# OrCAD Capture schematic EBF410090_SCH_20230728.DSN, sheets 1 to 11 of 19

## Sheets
1 12 WLAN BT: size A4; title: 野火_EBF RK3566 底板; rev: V1.0; note: WLAN & BT; note: https://yehuosm.tmall.com
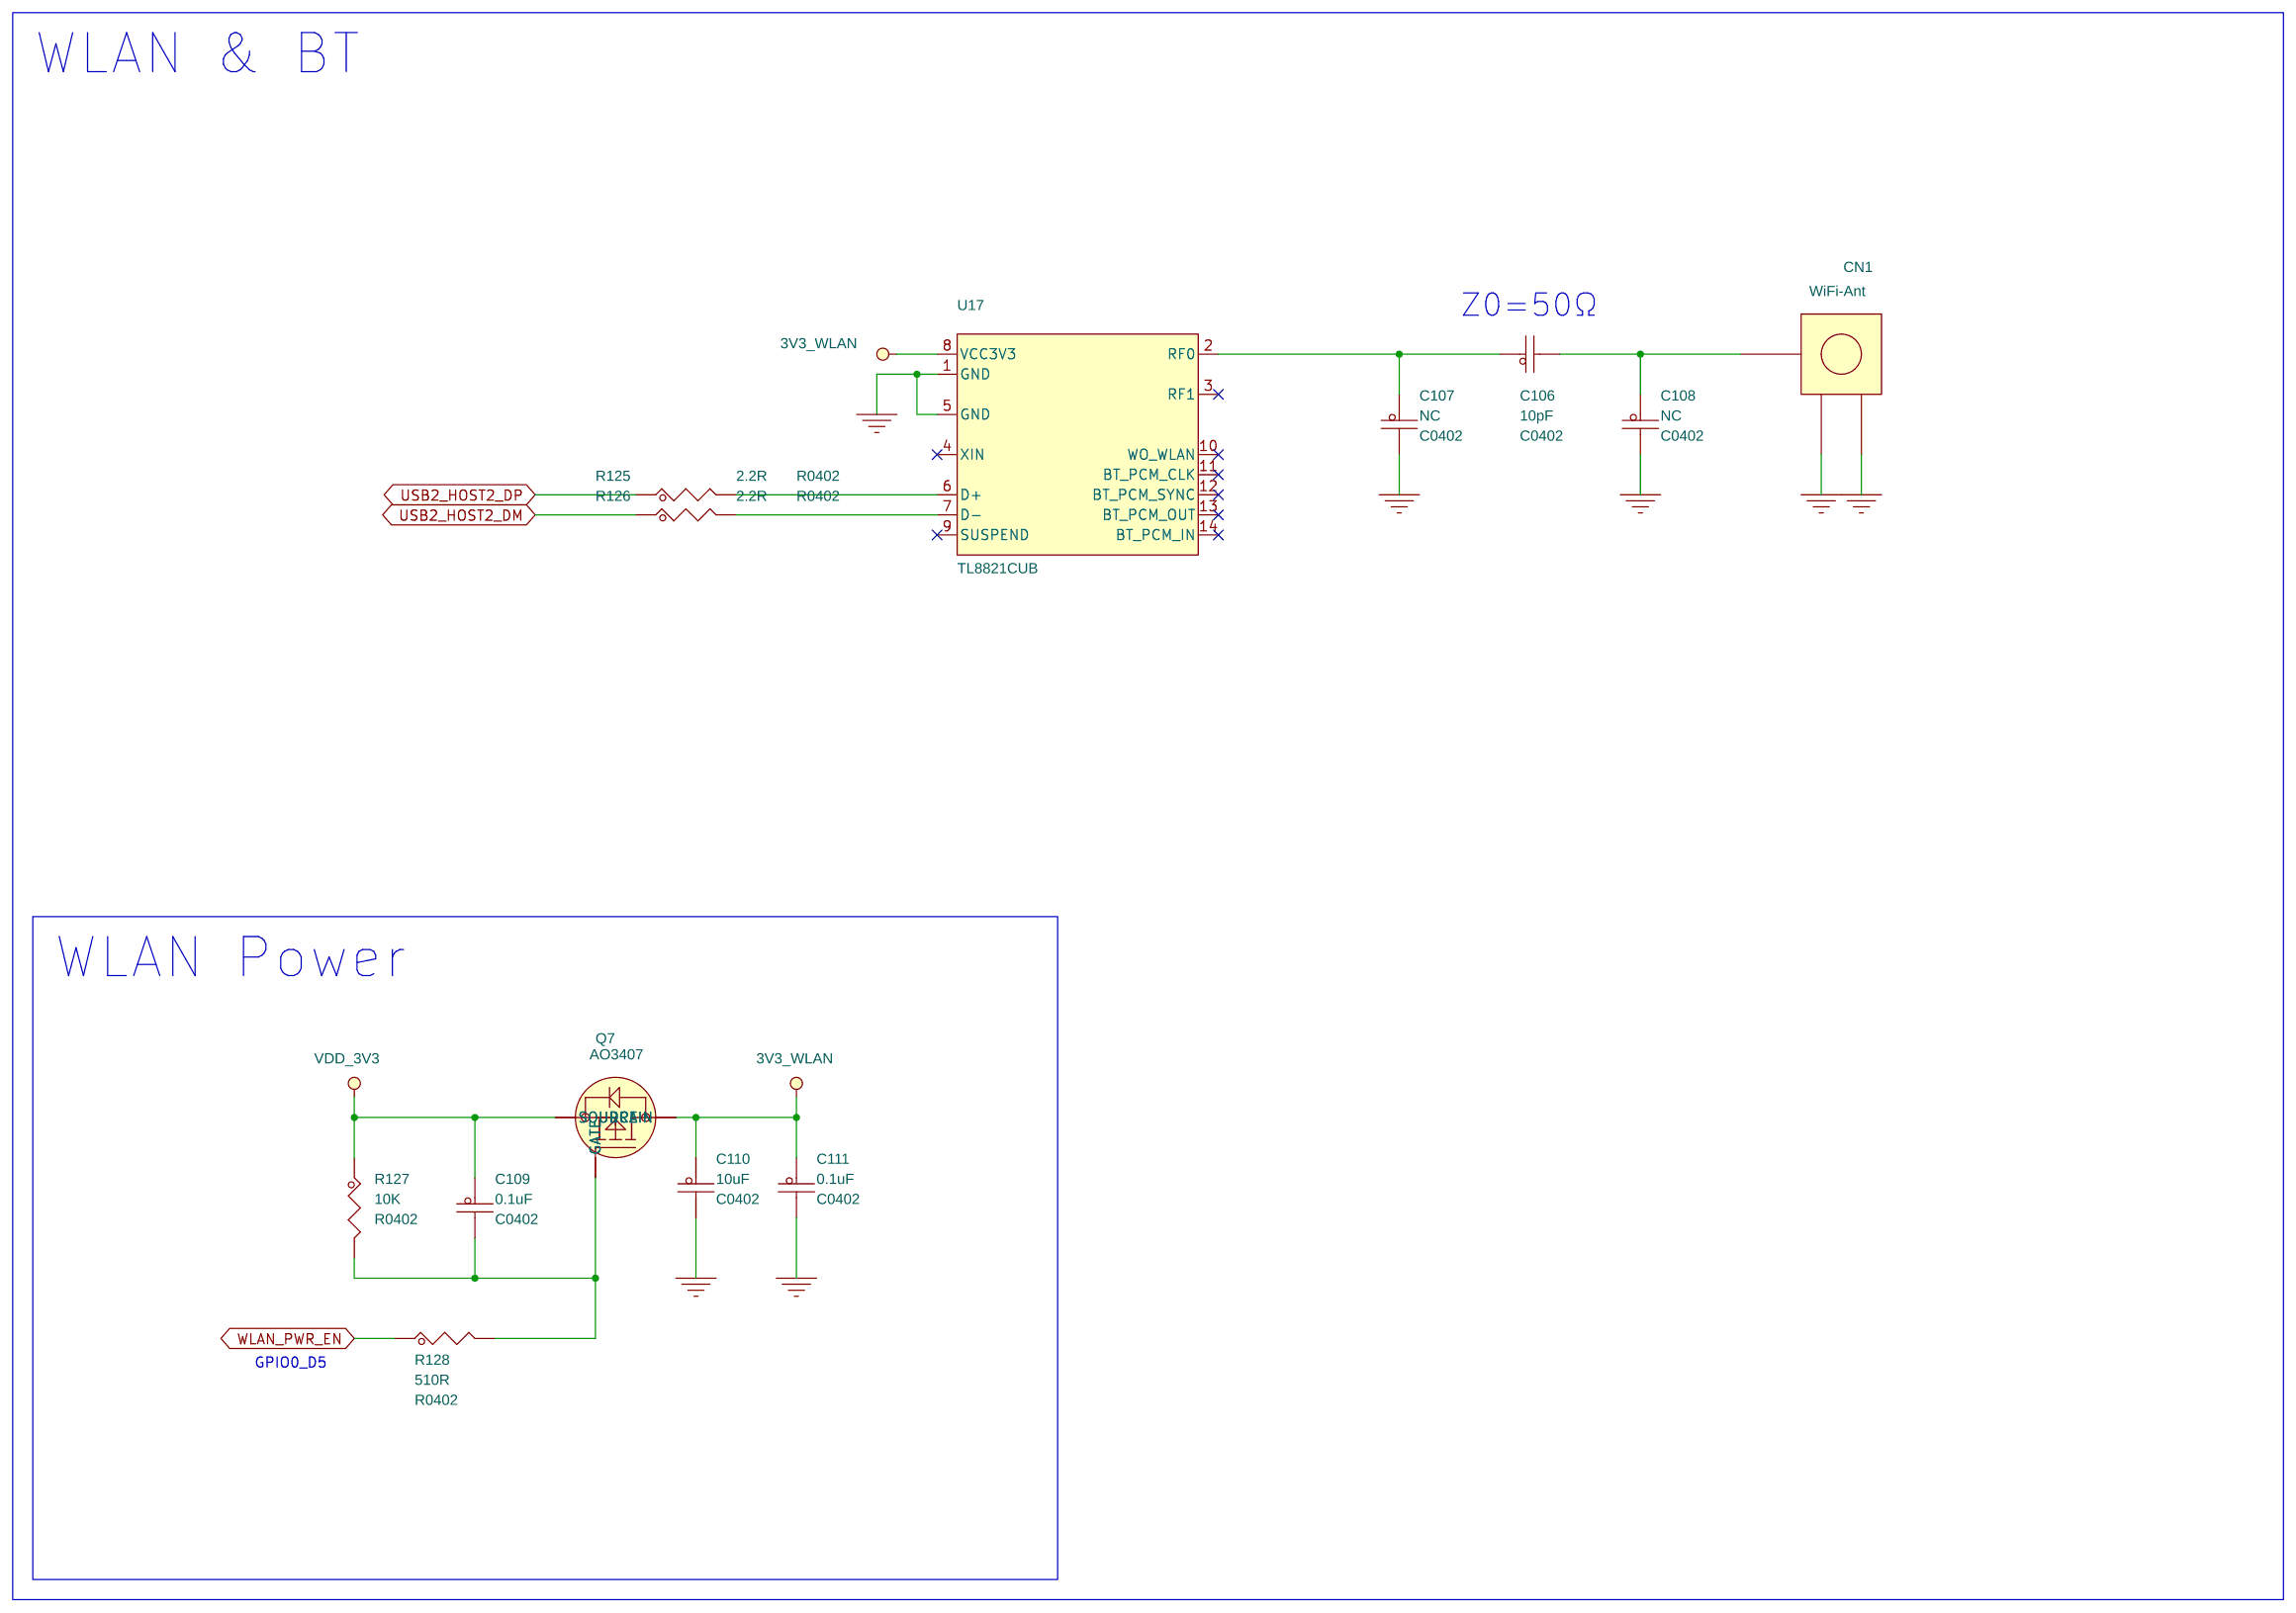
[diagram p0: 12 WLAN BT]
2 01 Content: note: Content
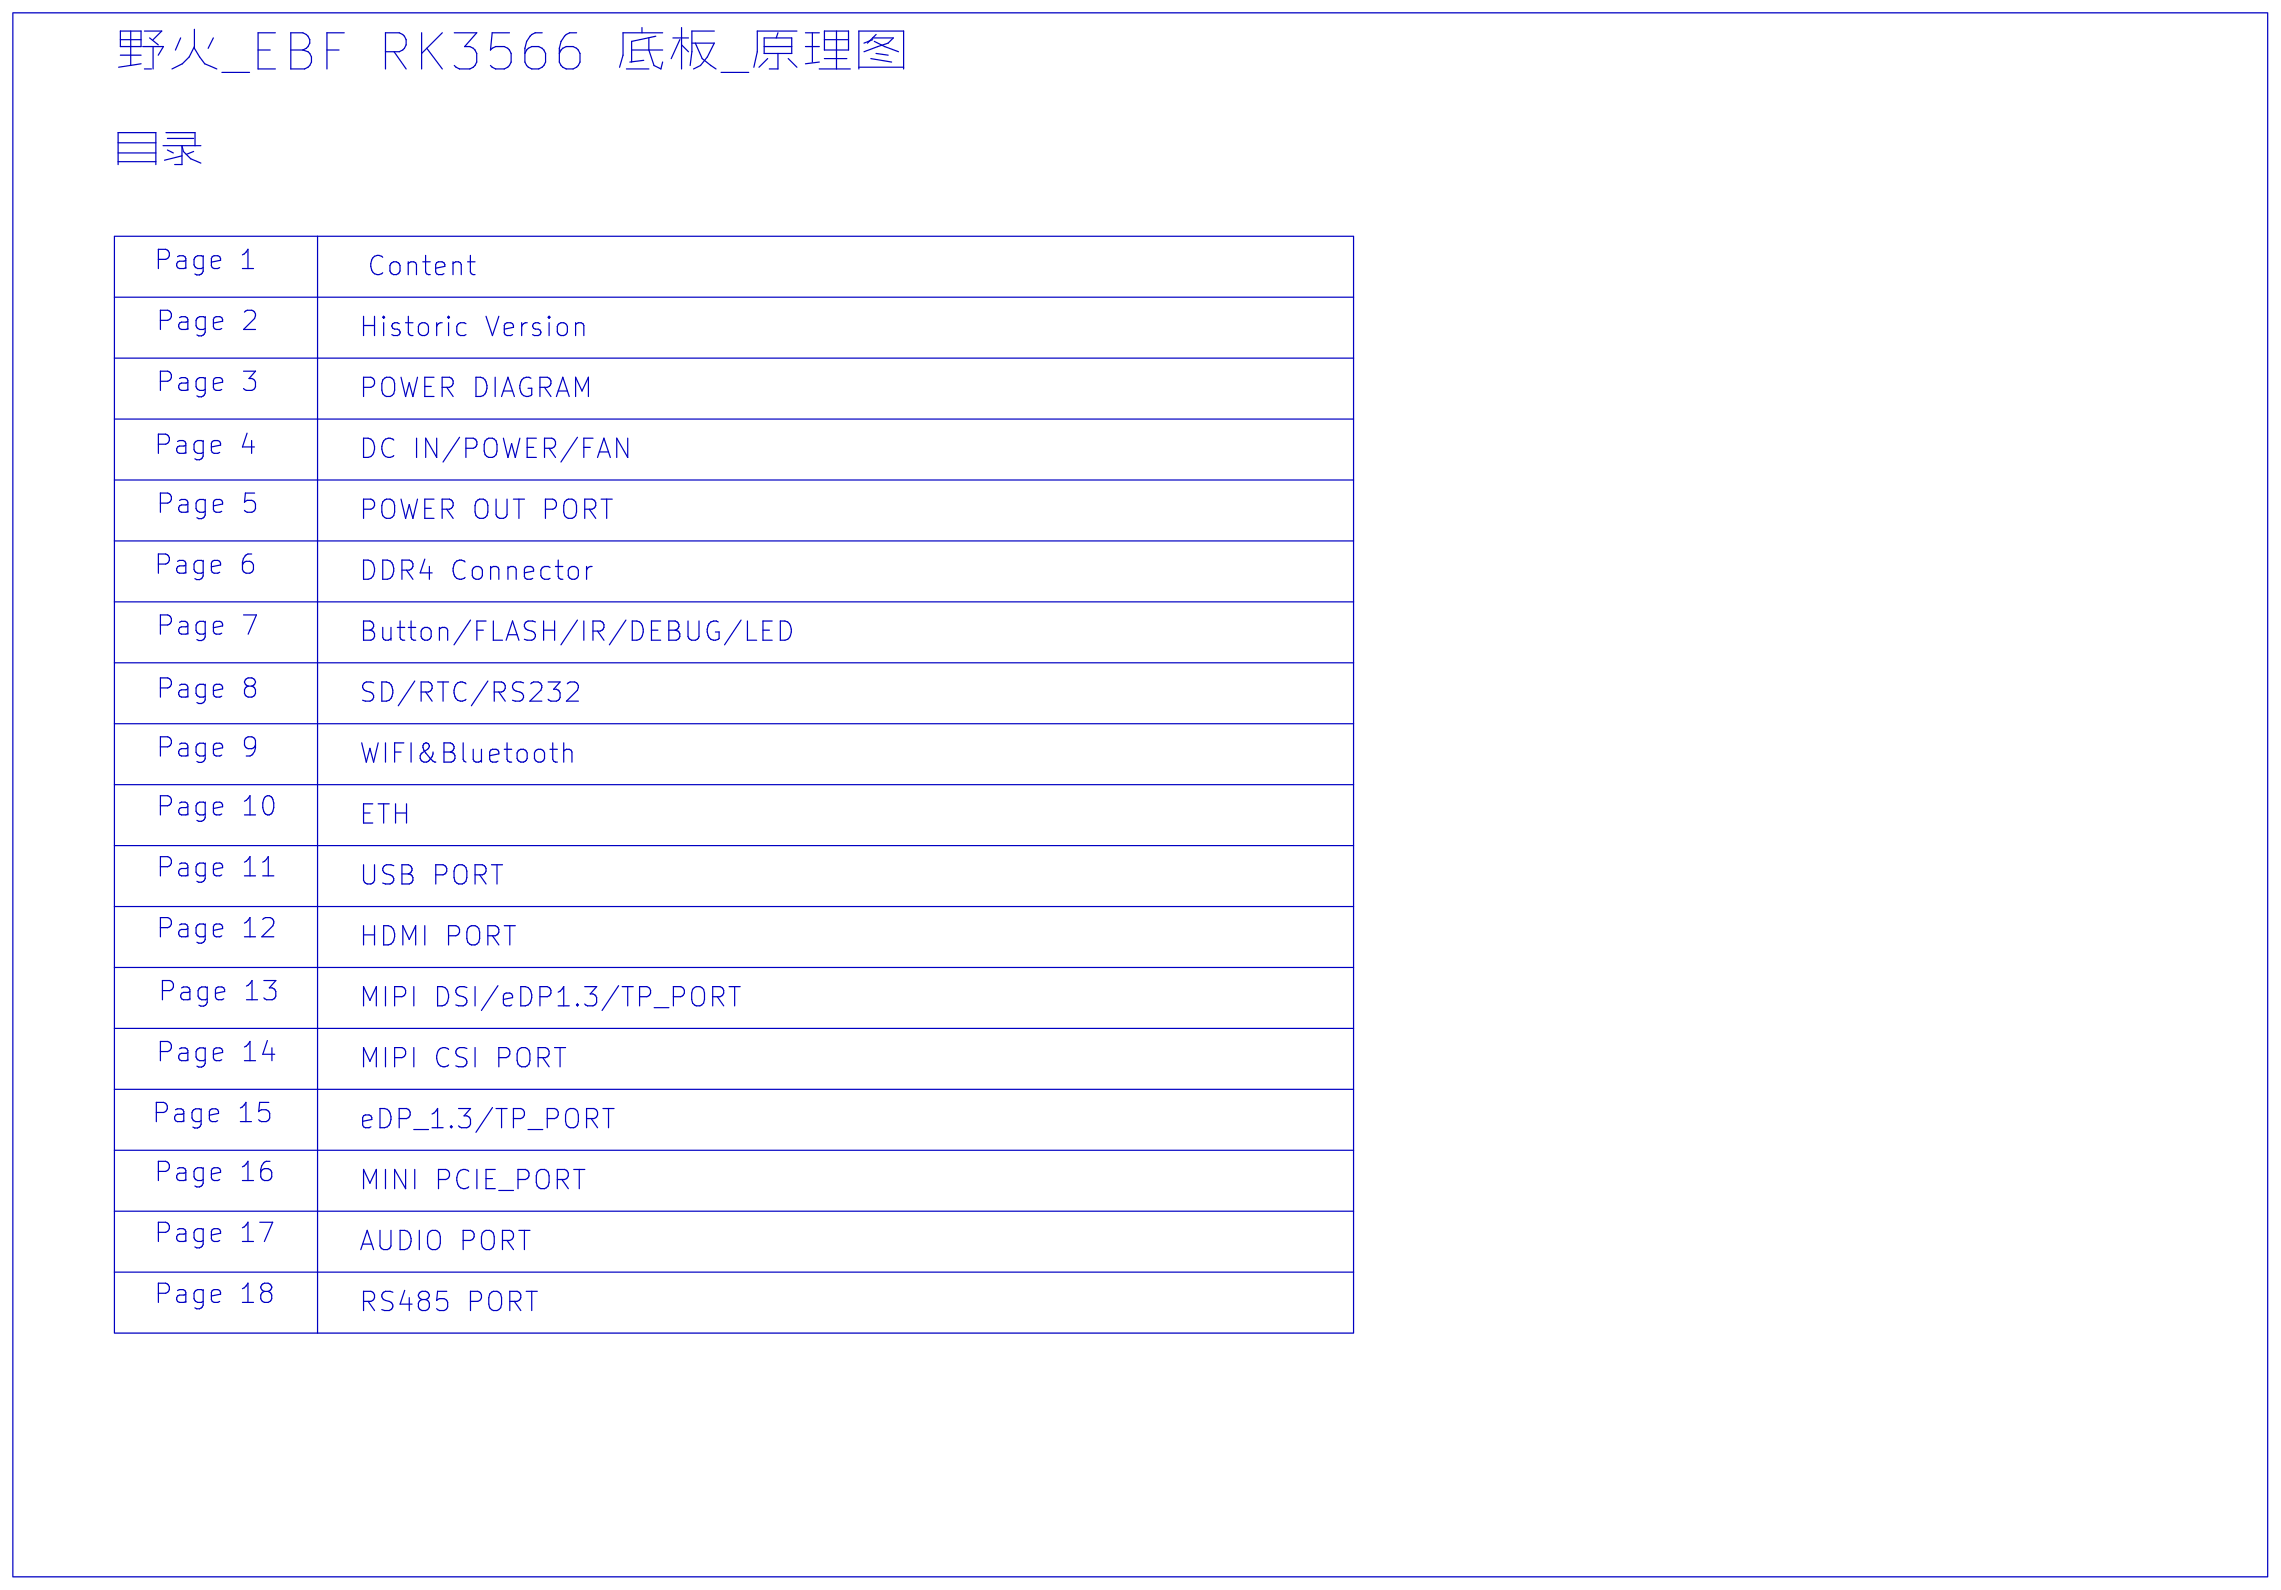
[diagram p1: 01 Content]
3 02 Historic Version: note: Historic Version
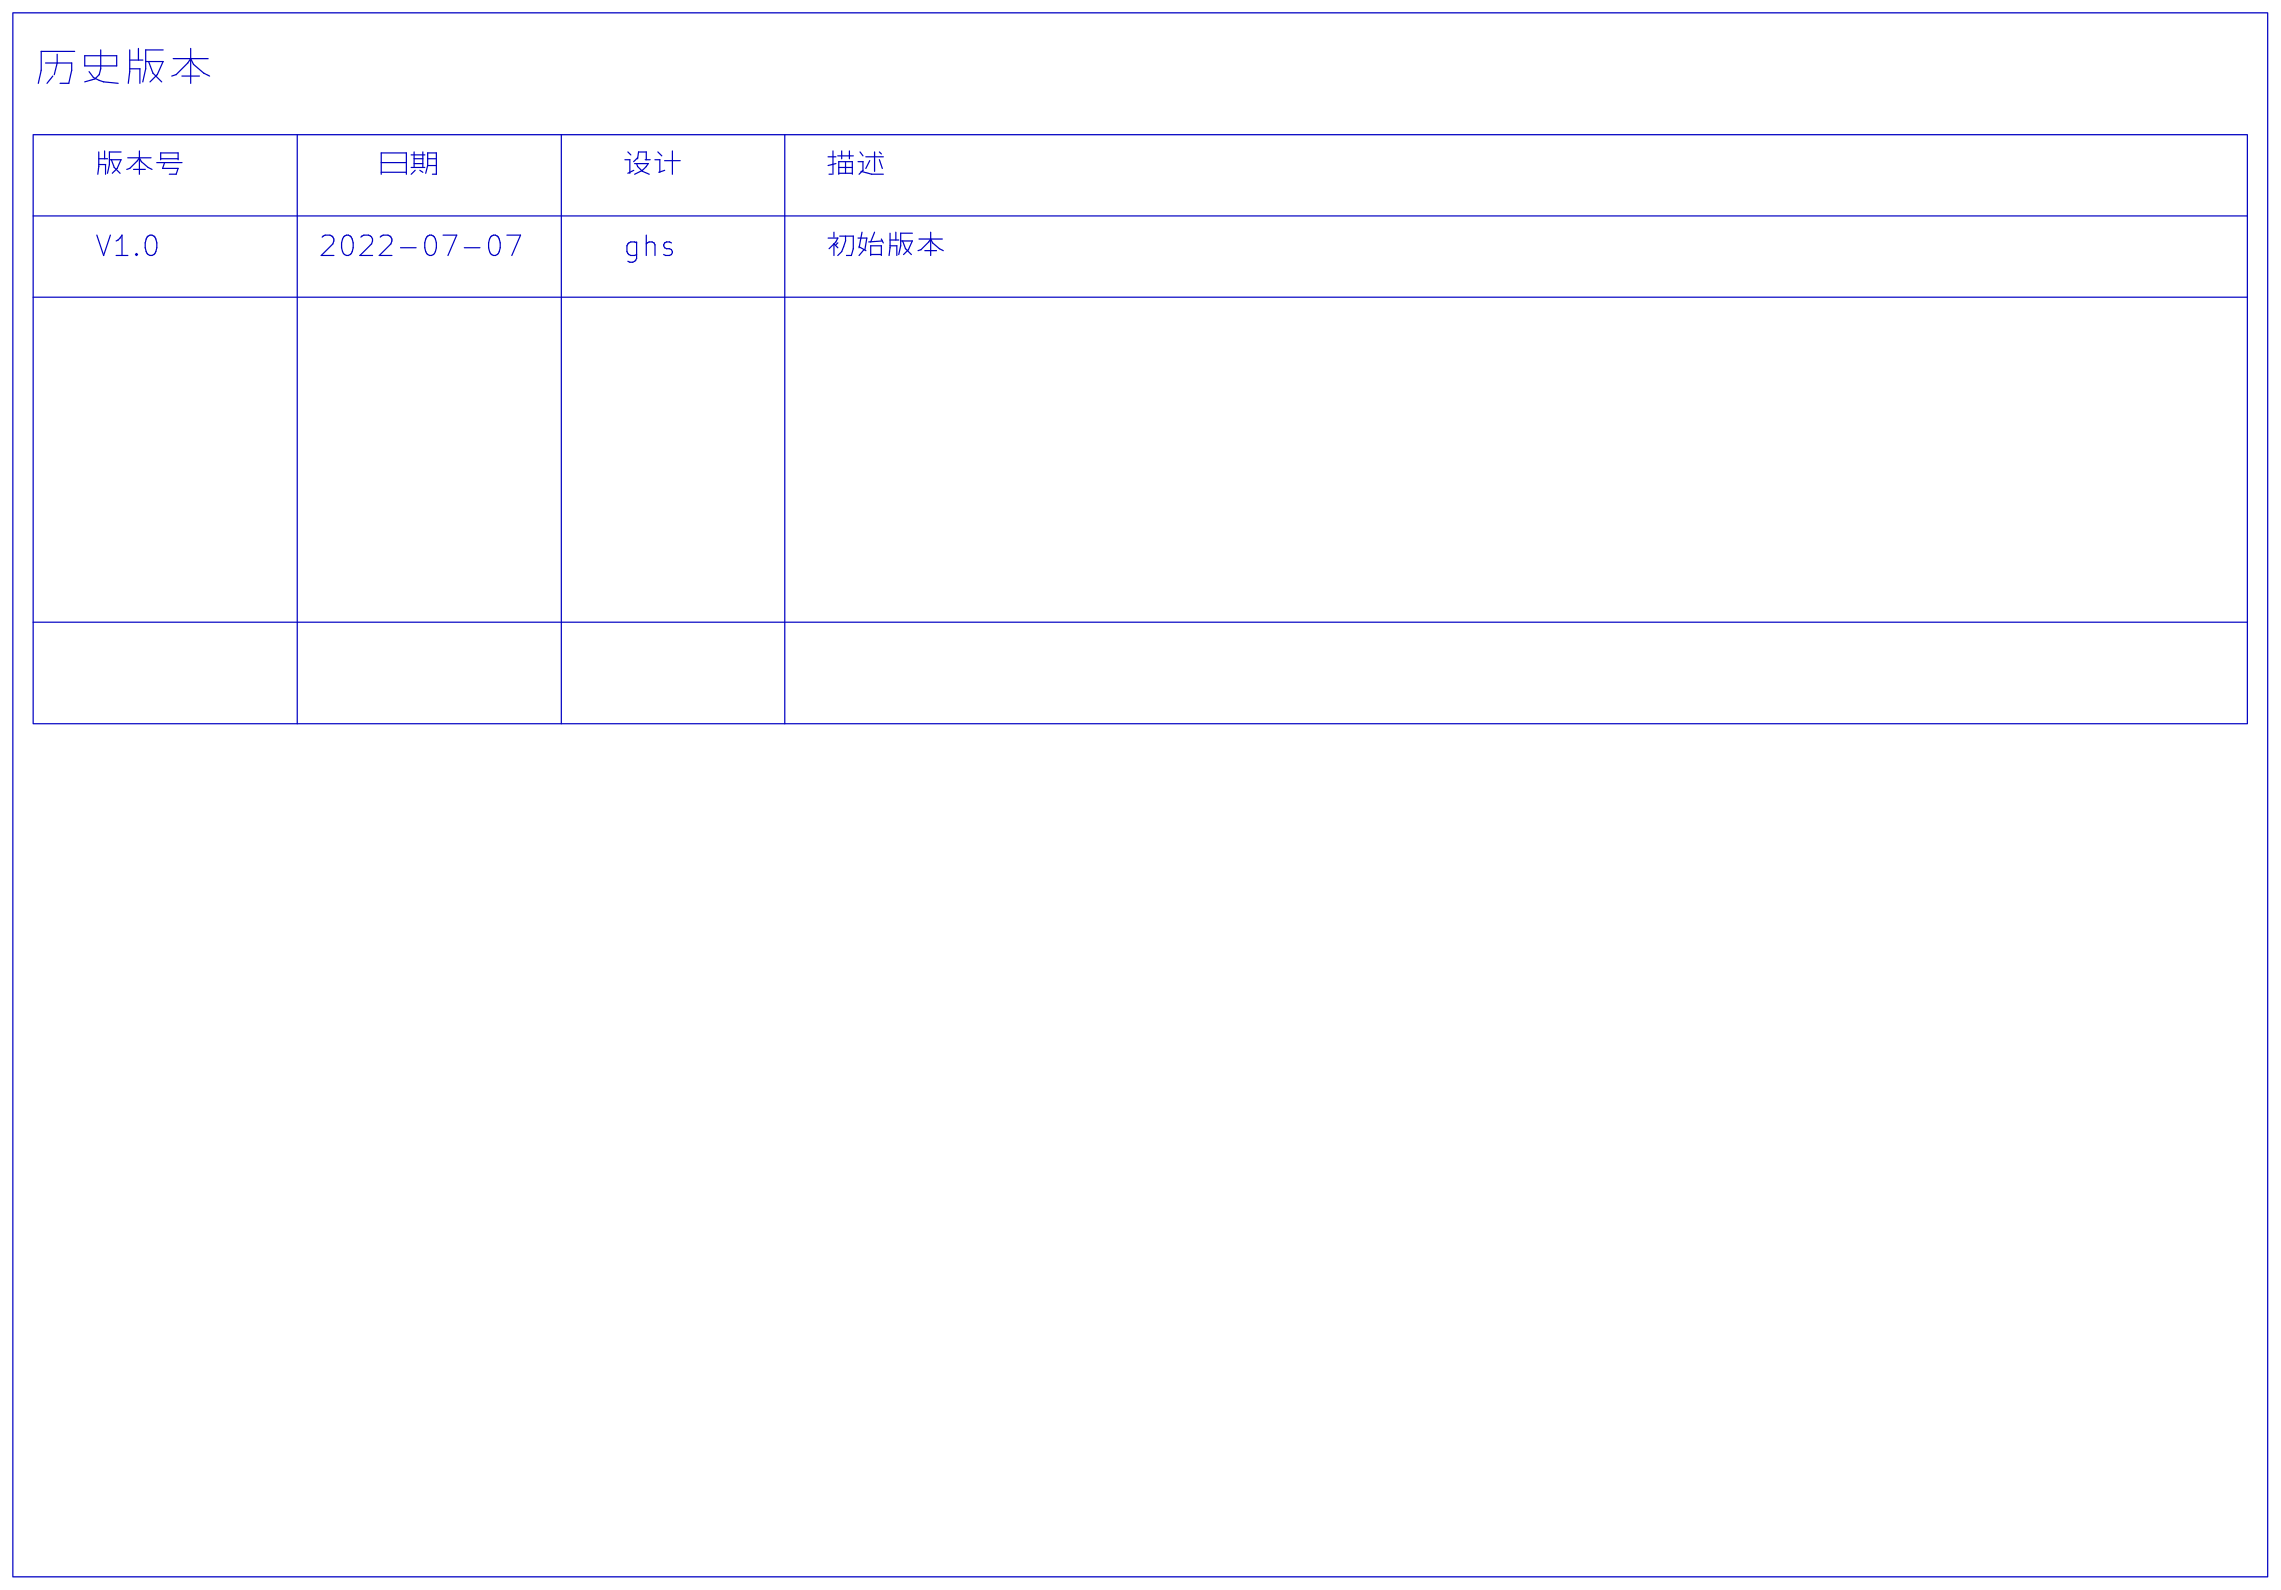
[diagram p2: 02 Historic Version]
4 03 POWER DIAGRAM: note: POWER DIAGRAM
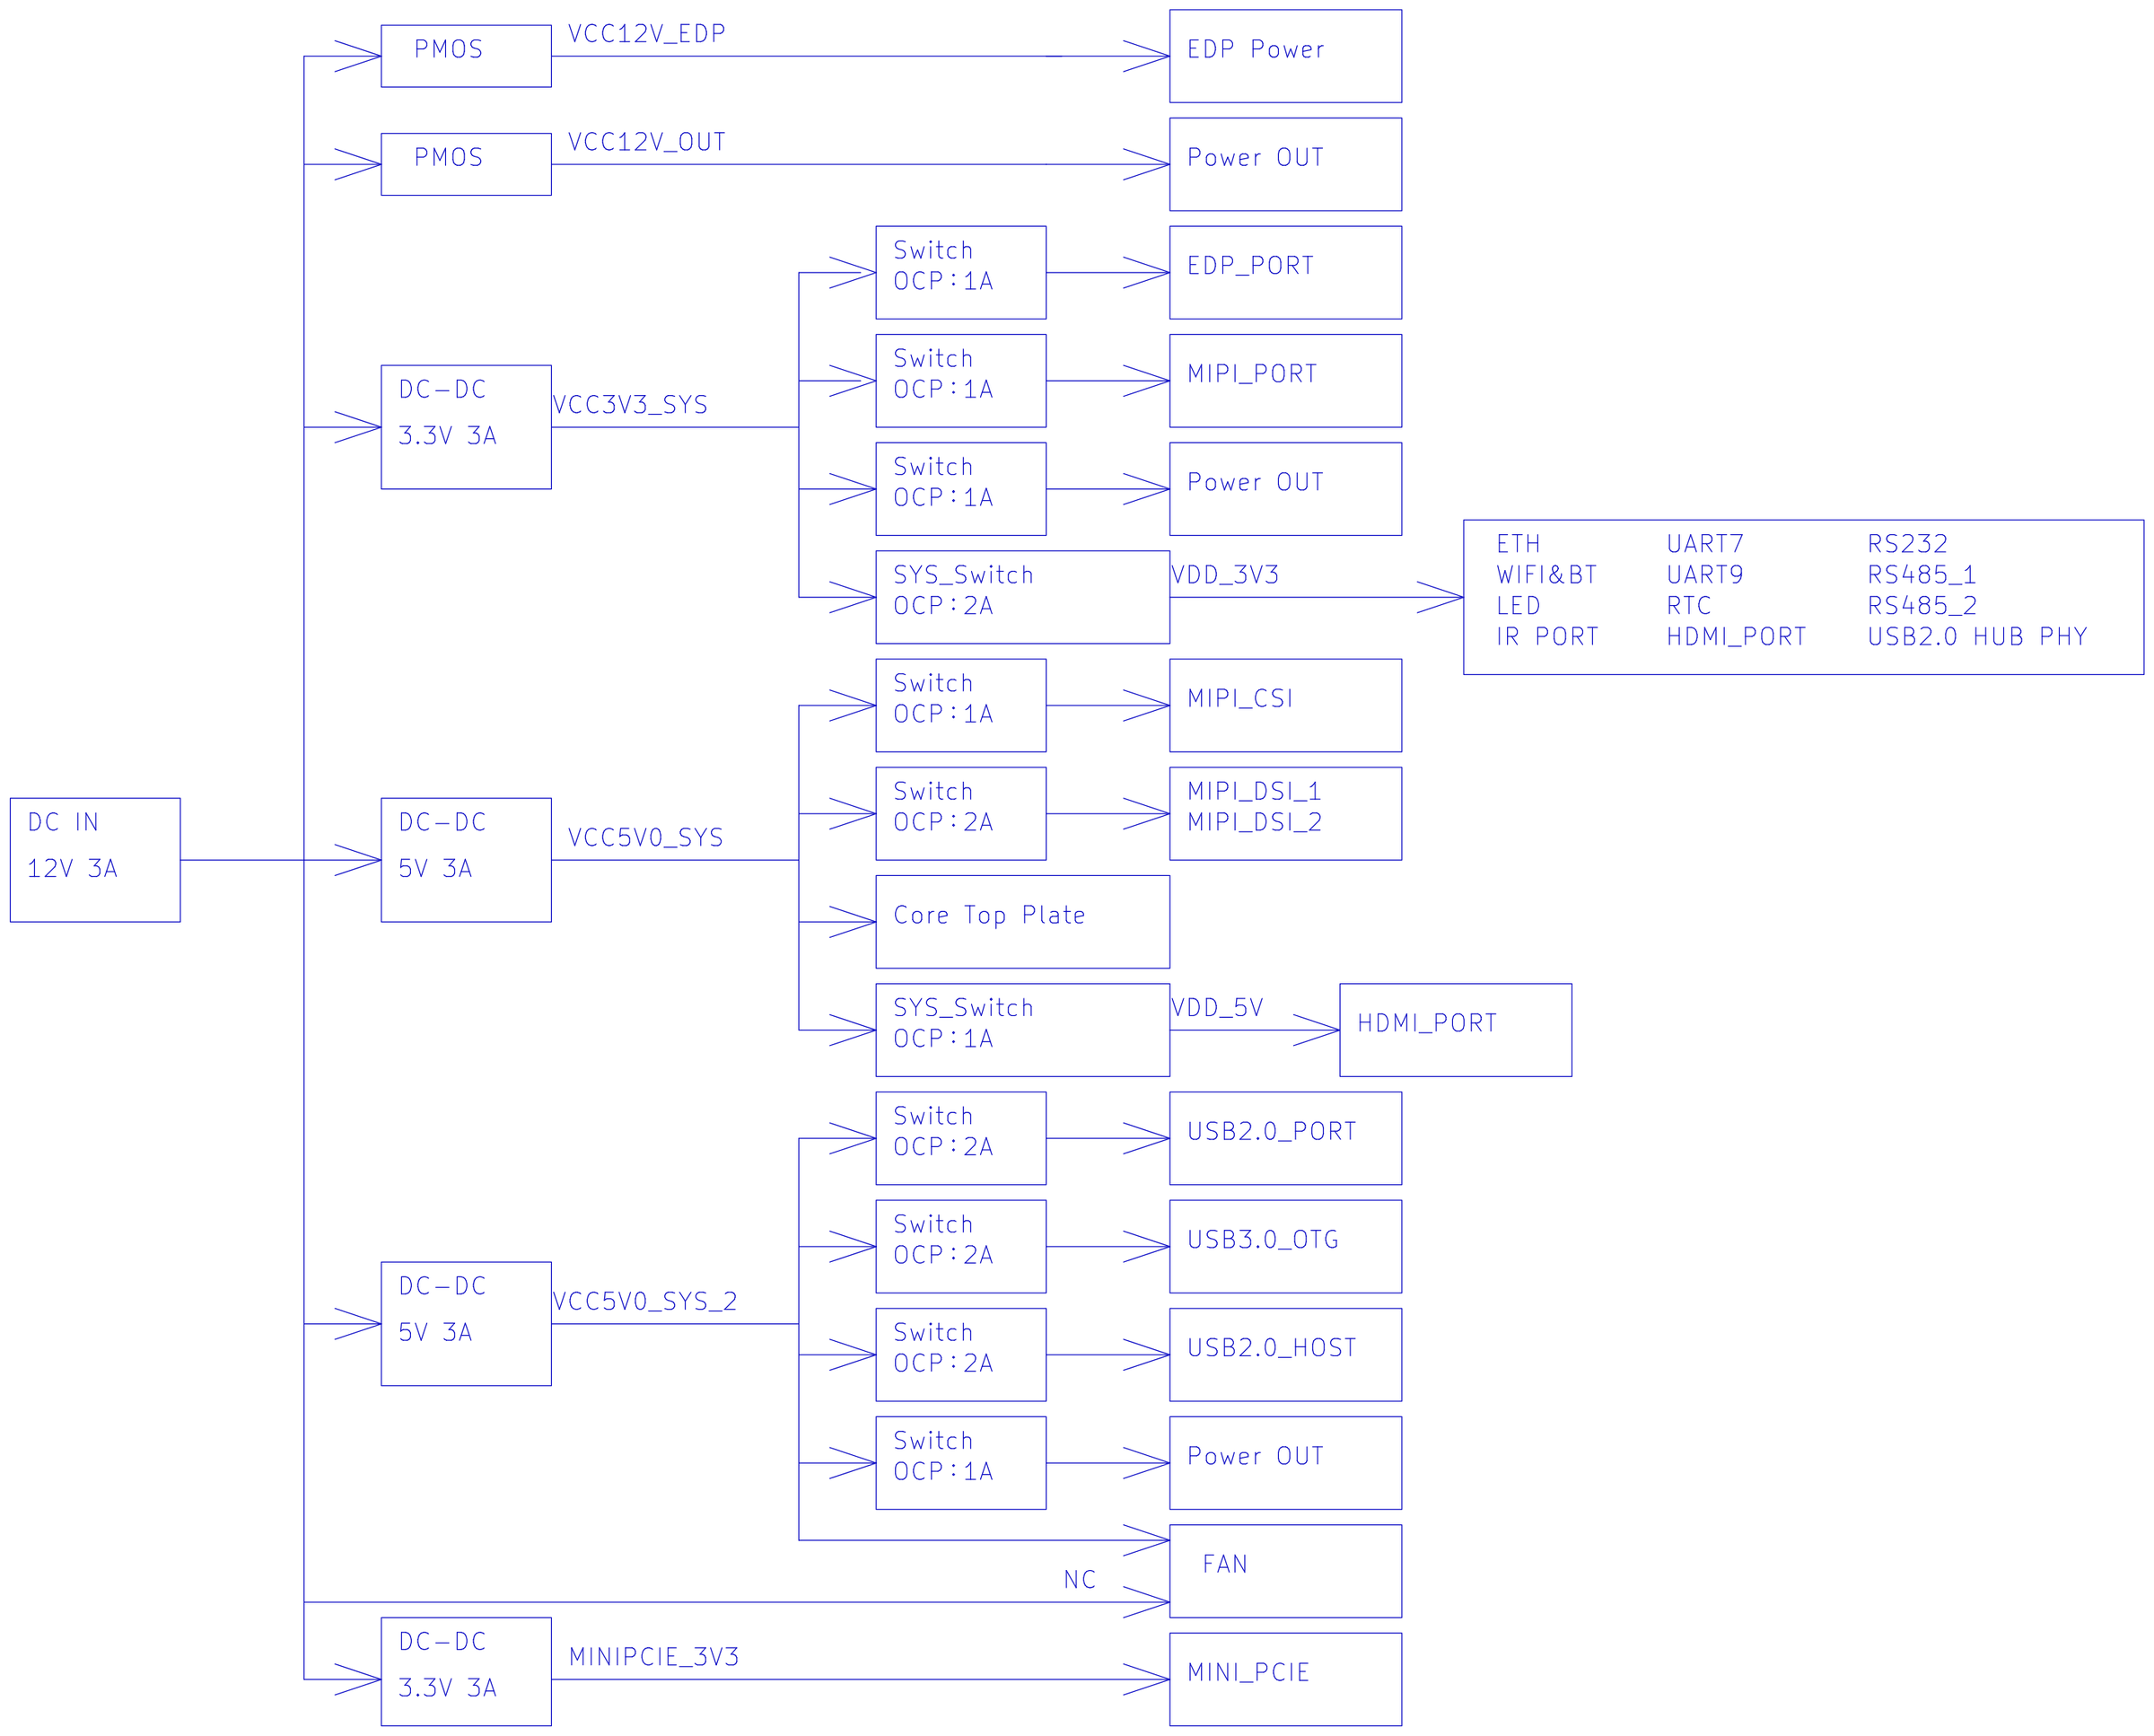
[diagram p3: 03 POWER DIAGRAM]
5 05 POWER OUT PORT: size A4; note: POWER OUT PORT
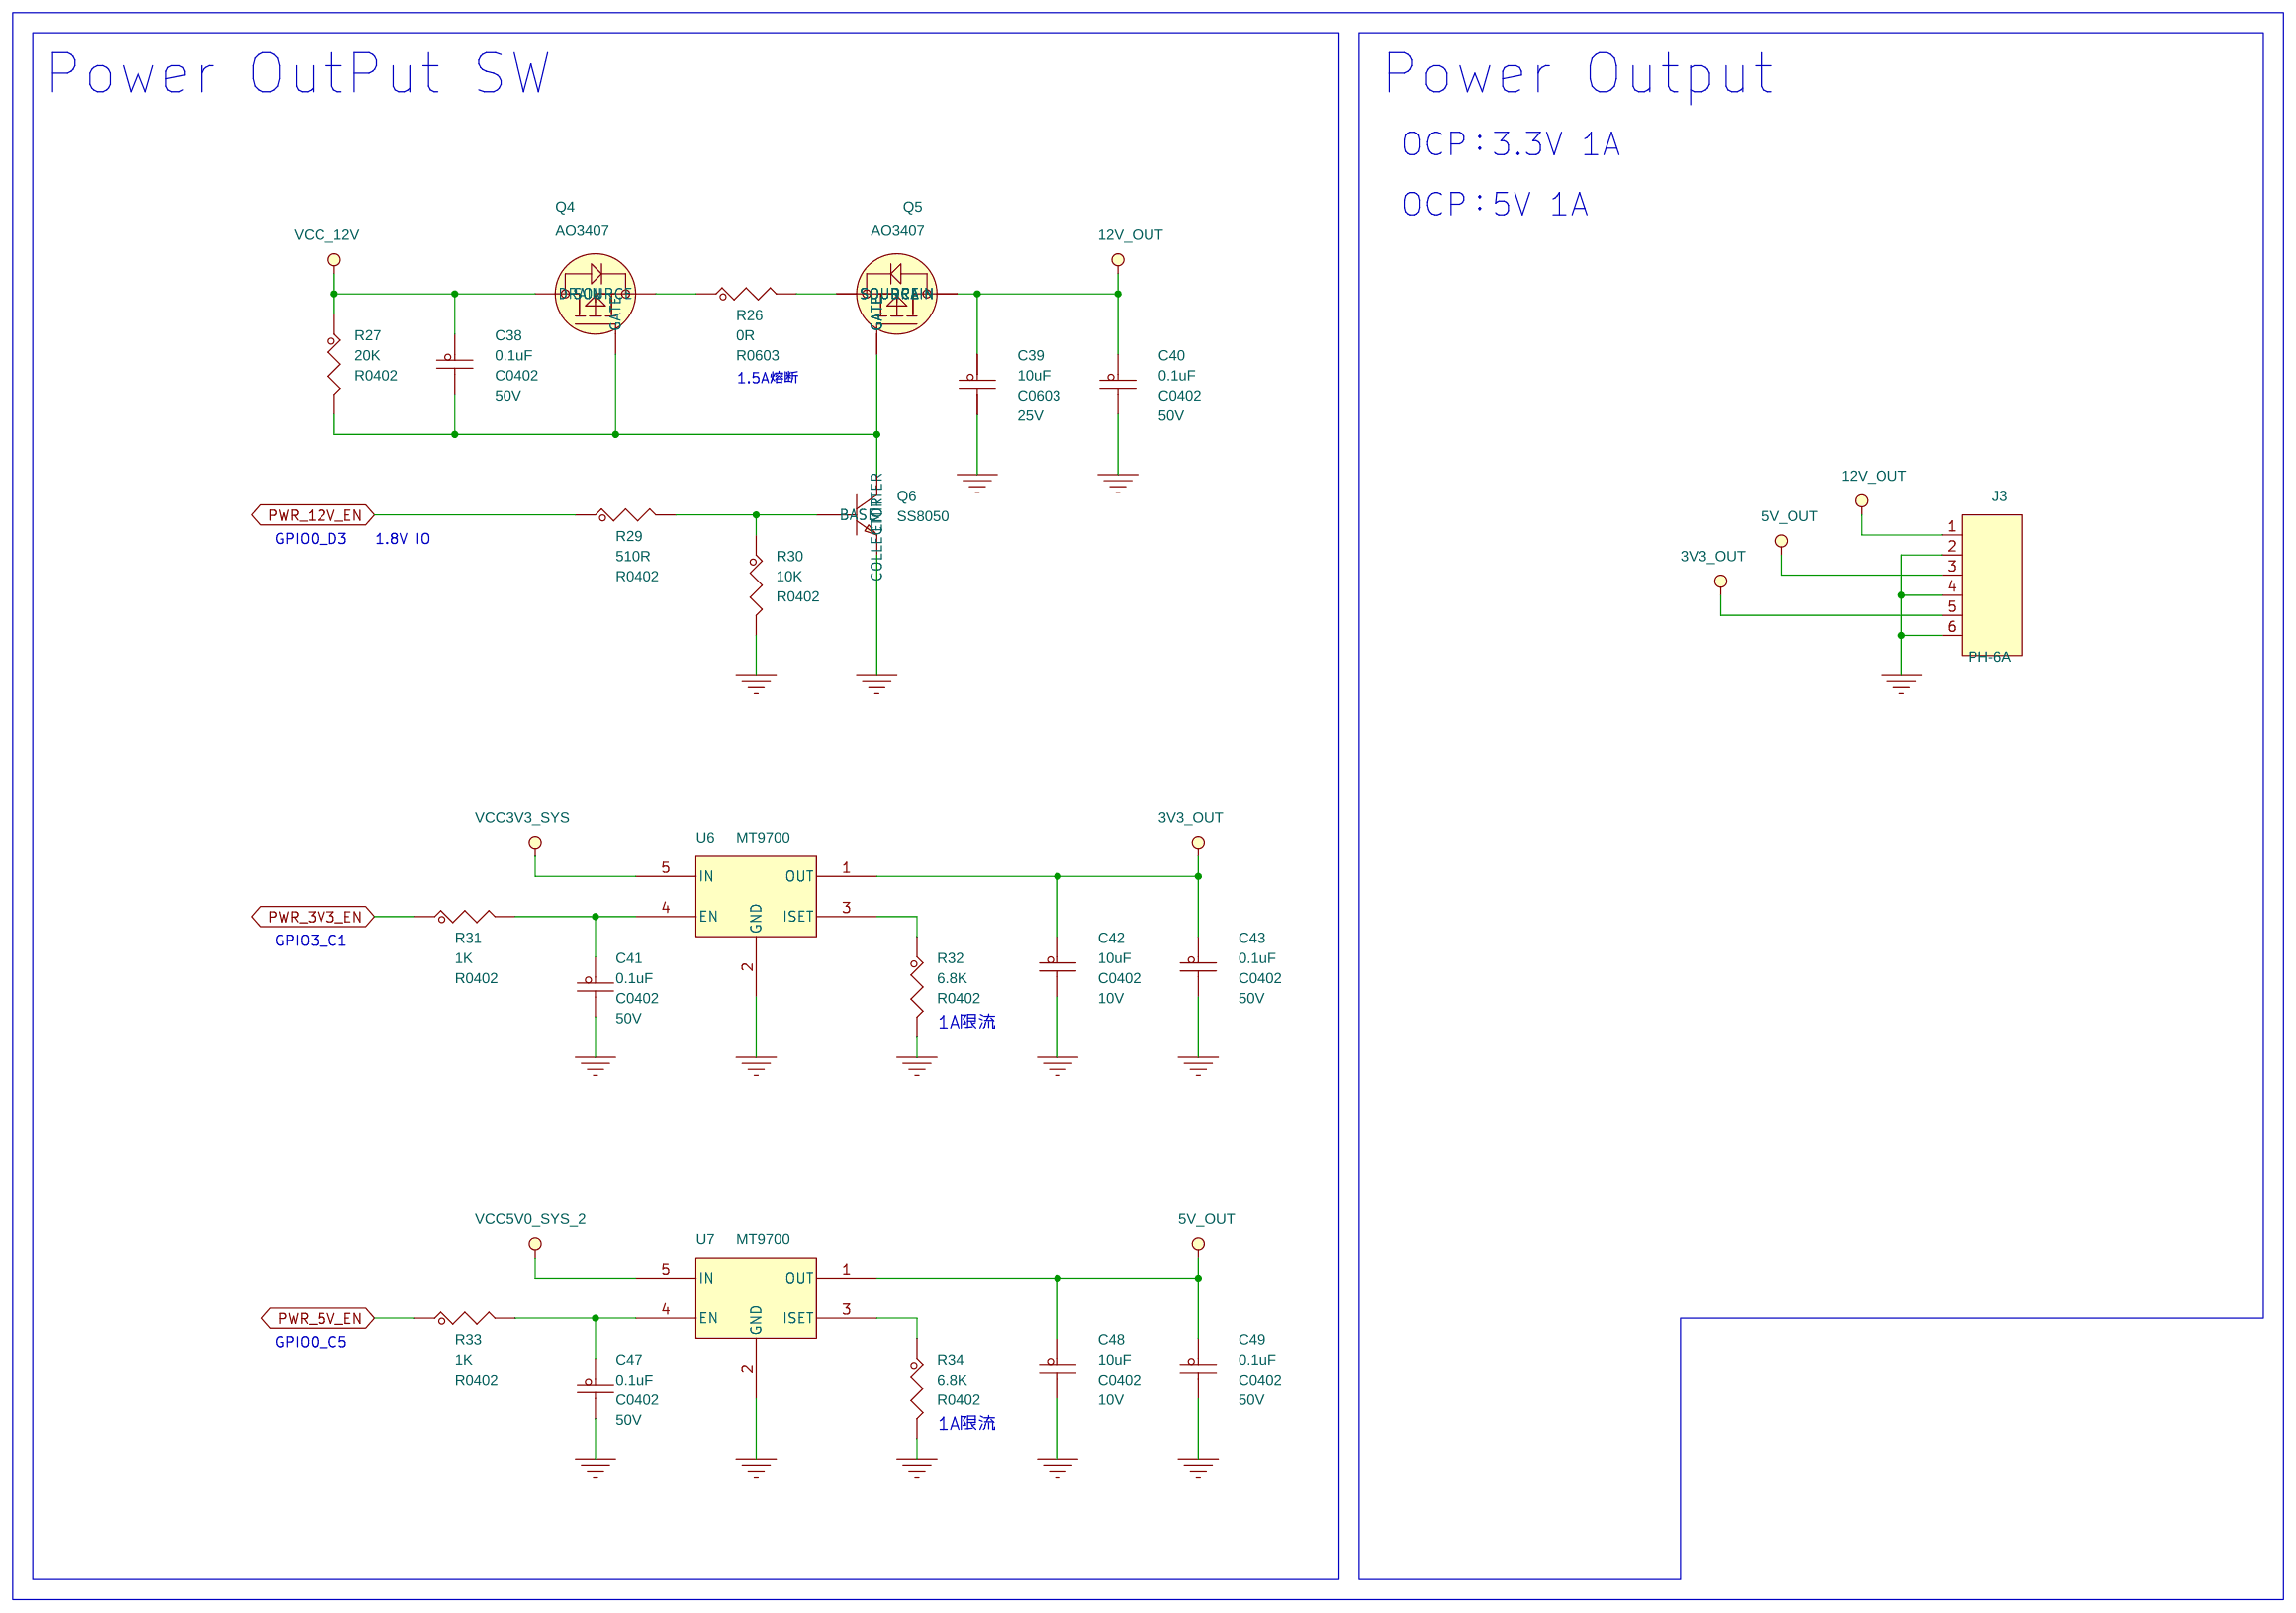
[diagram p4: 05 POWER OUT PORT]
6 06 DDR4 Connector: size A2; title: 野火_EBF RK3568 底板; note: DDR4 Connector
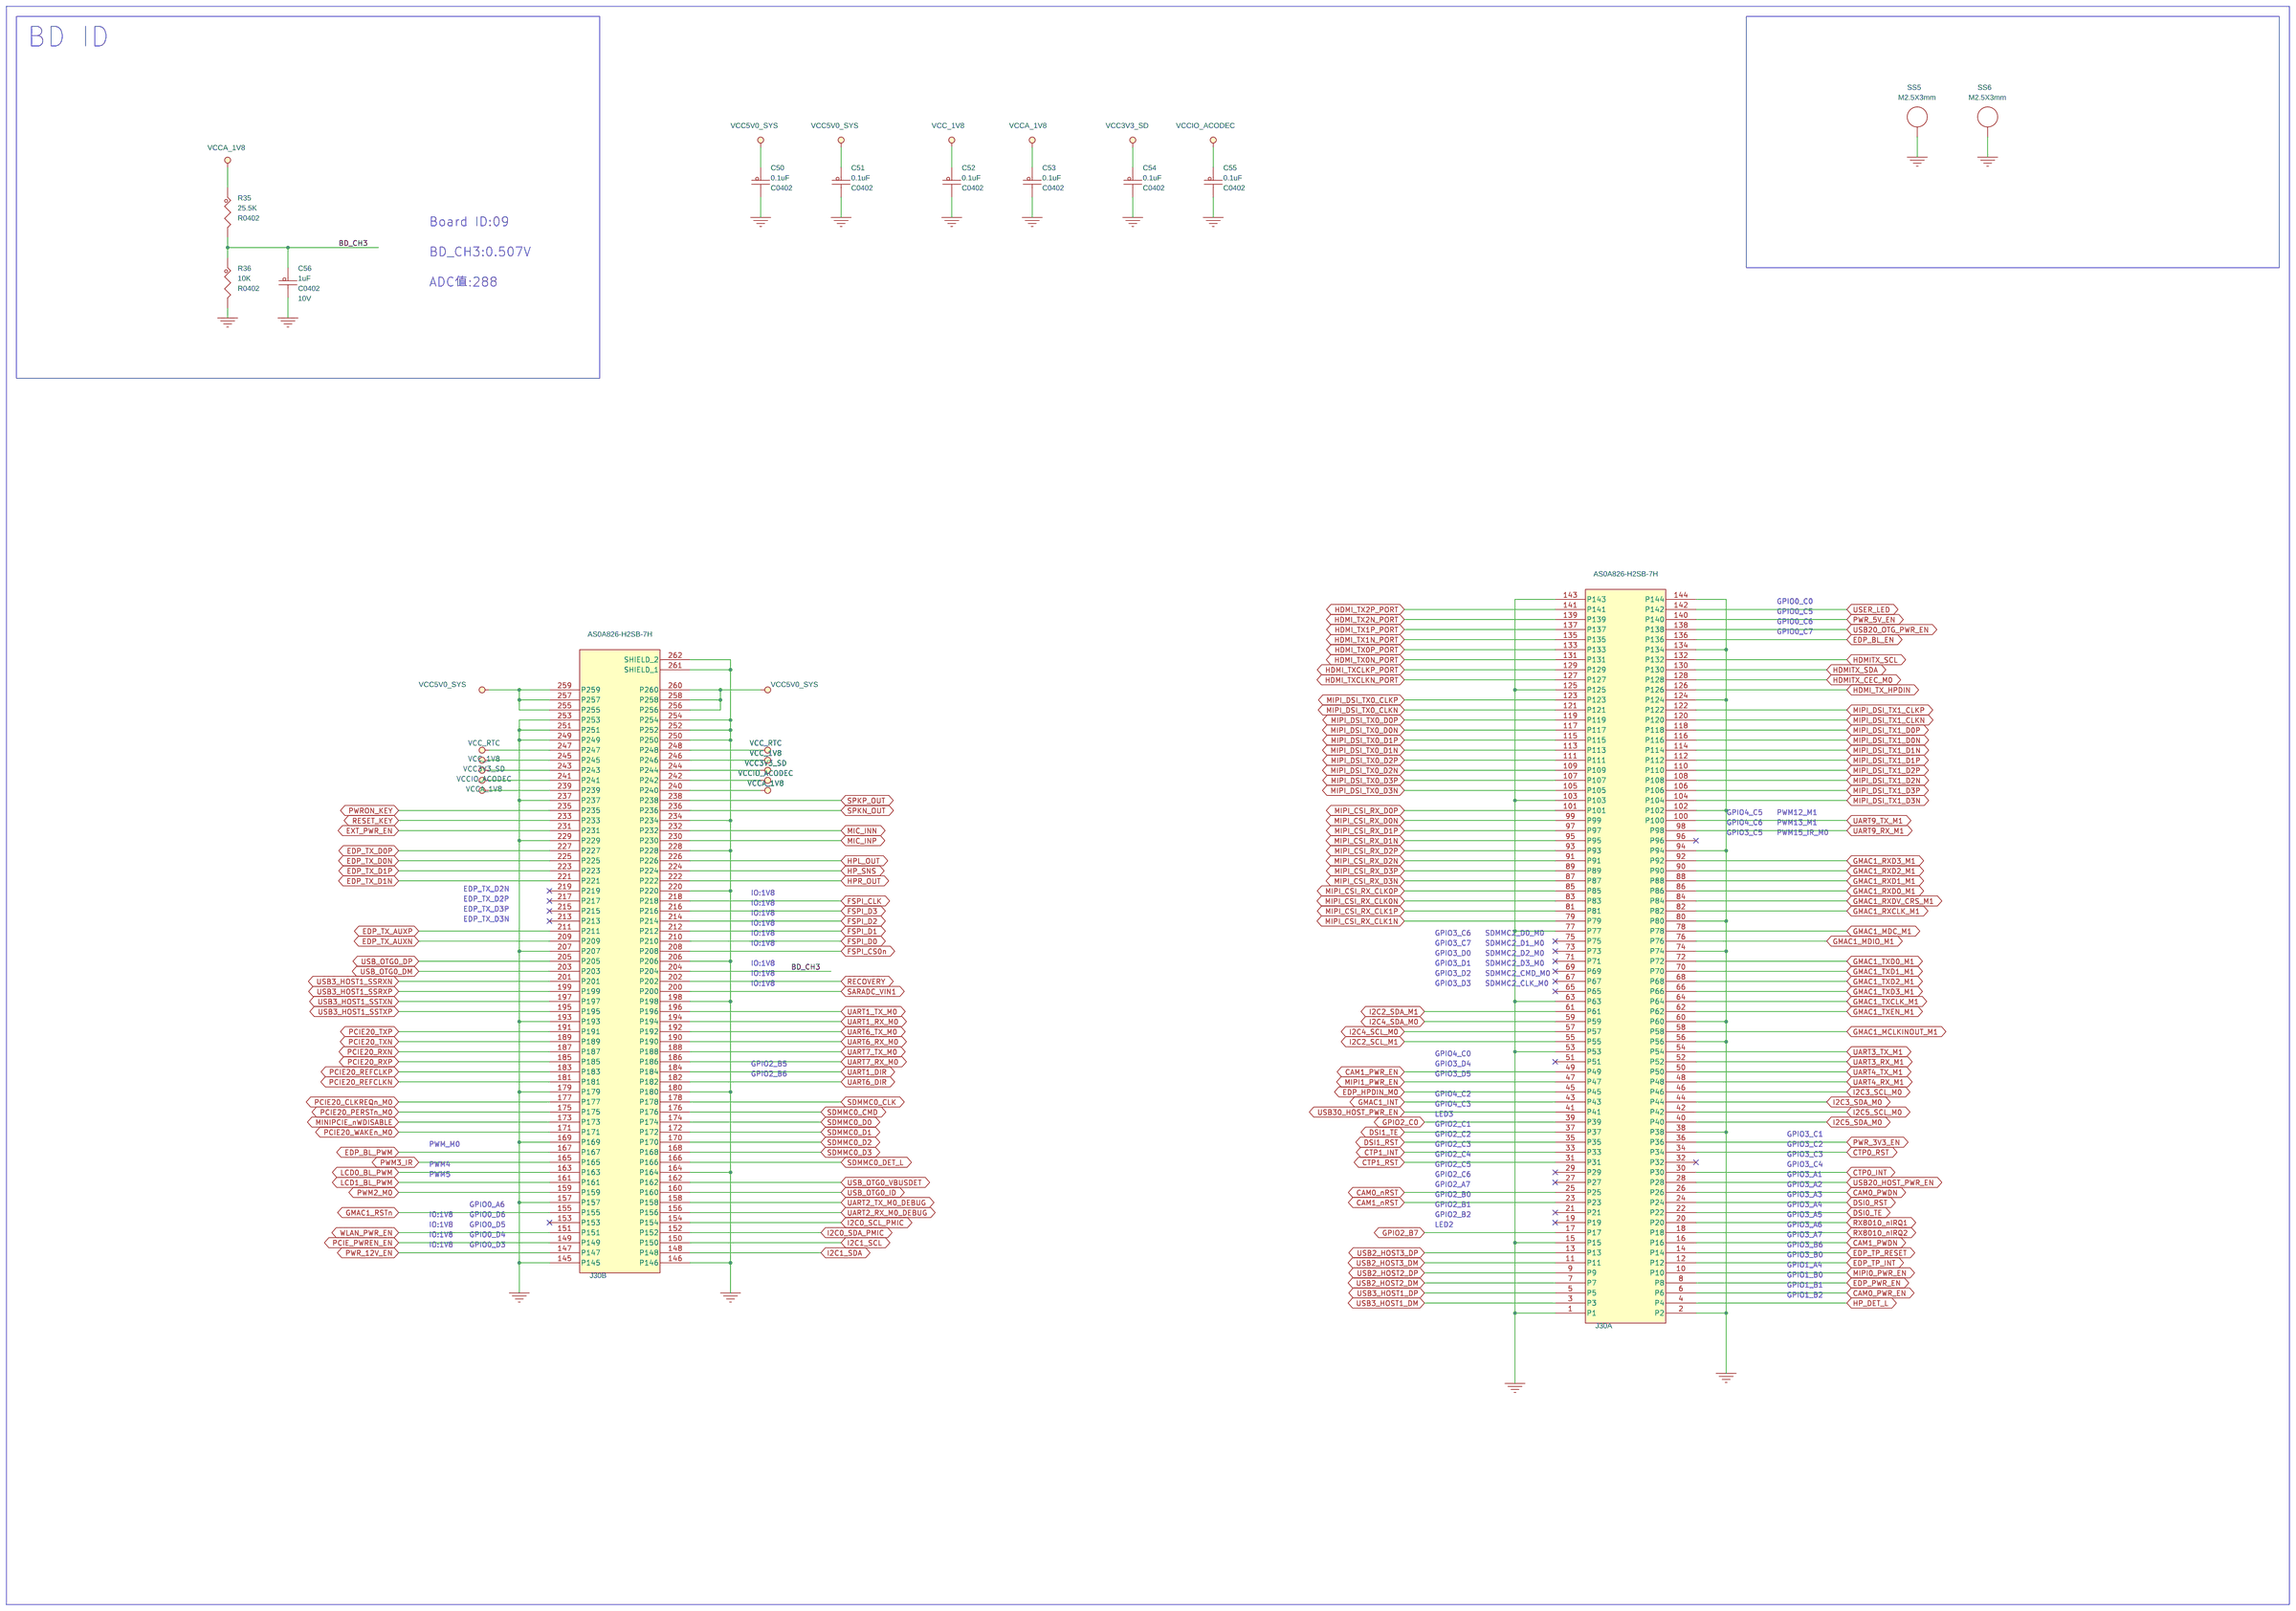
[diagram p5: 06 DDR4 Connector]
7 09 RS485 PORT: size A4; note: RS485 PORT
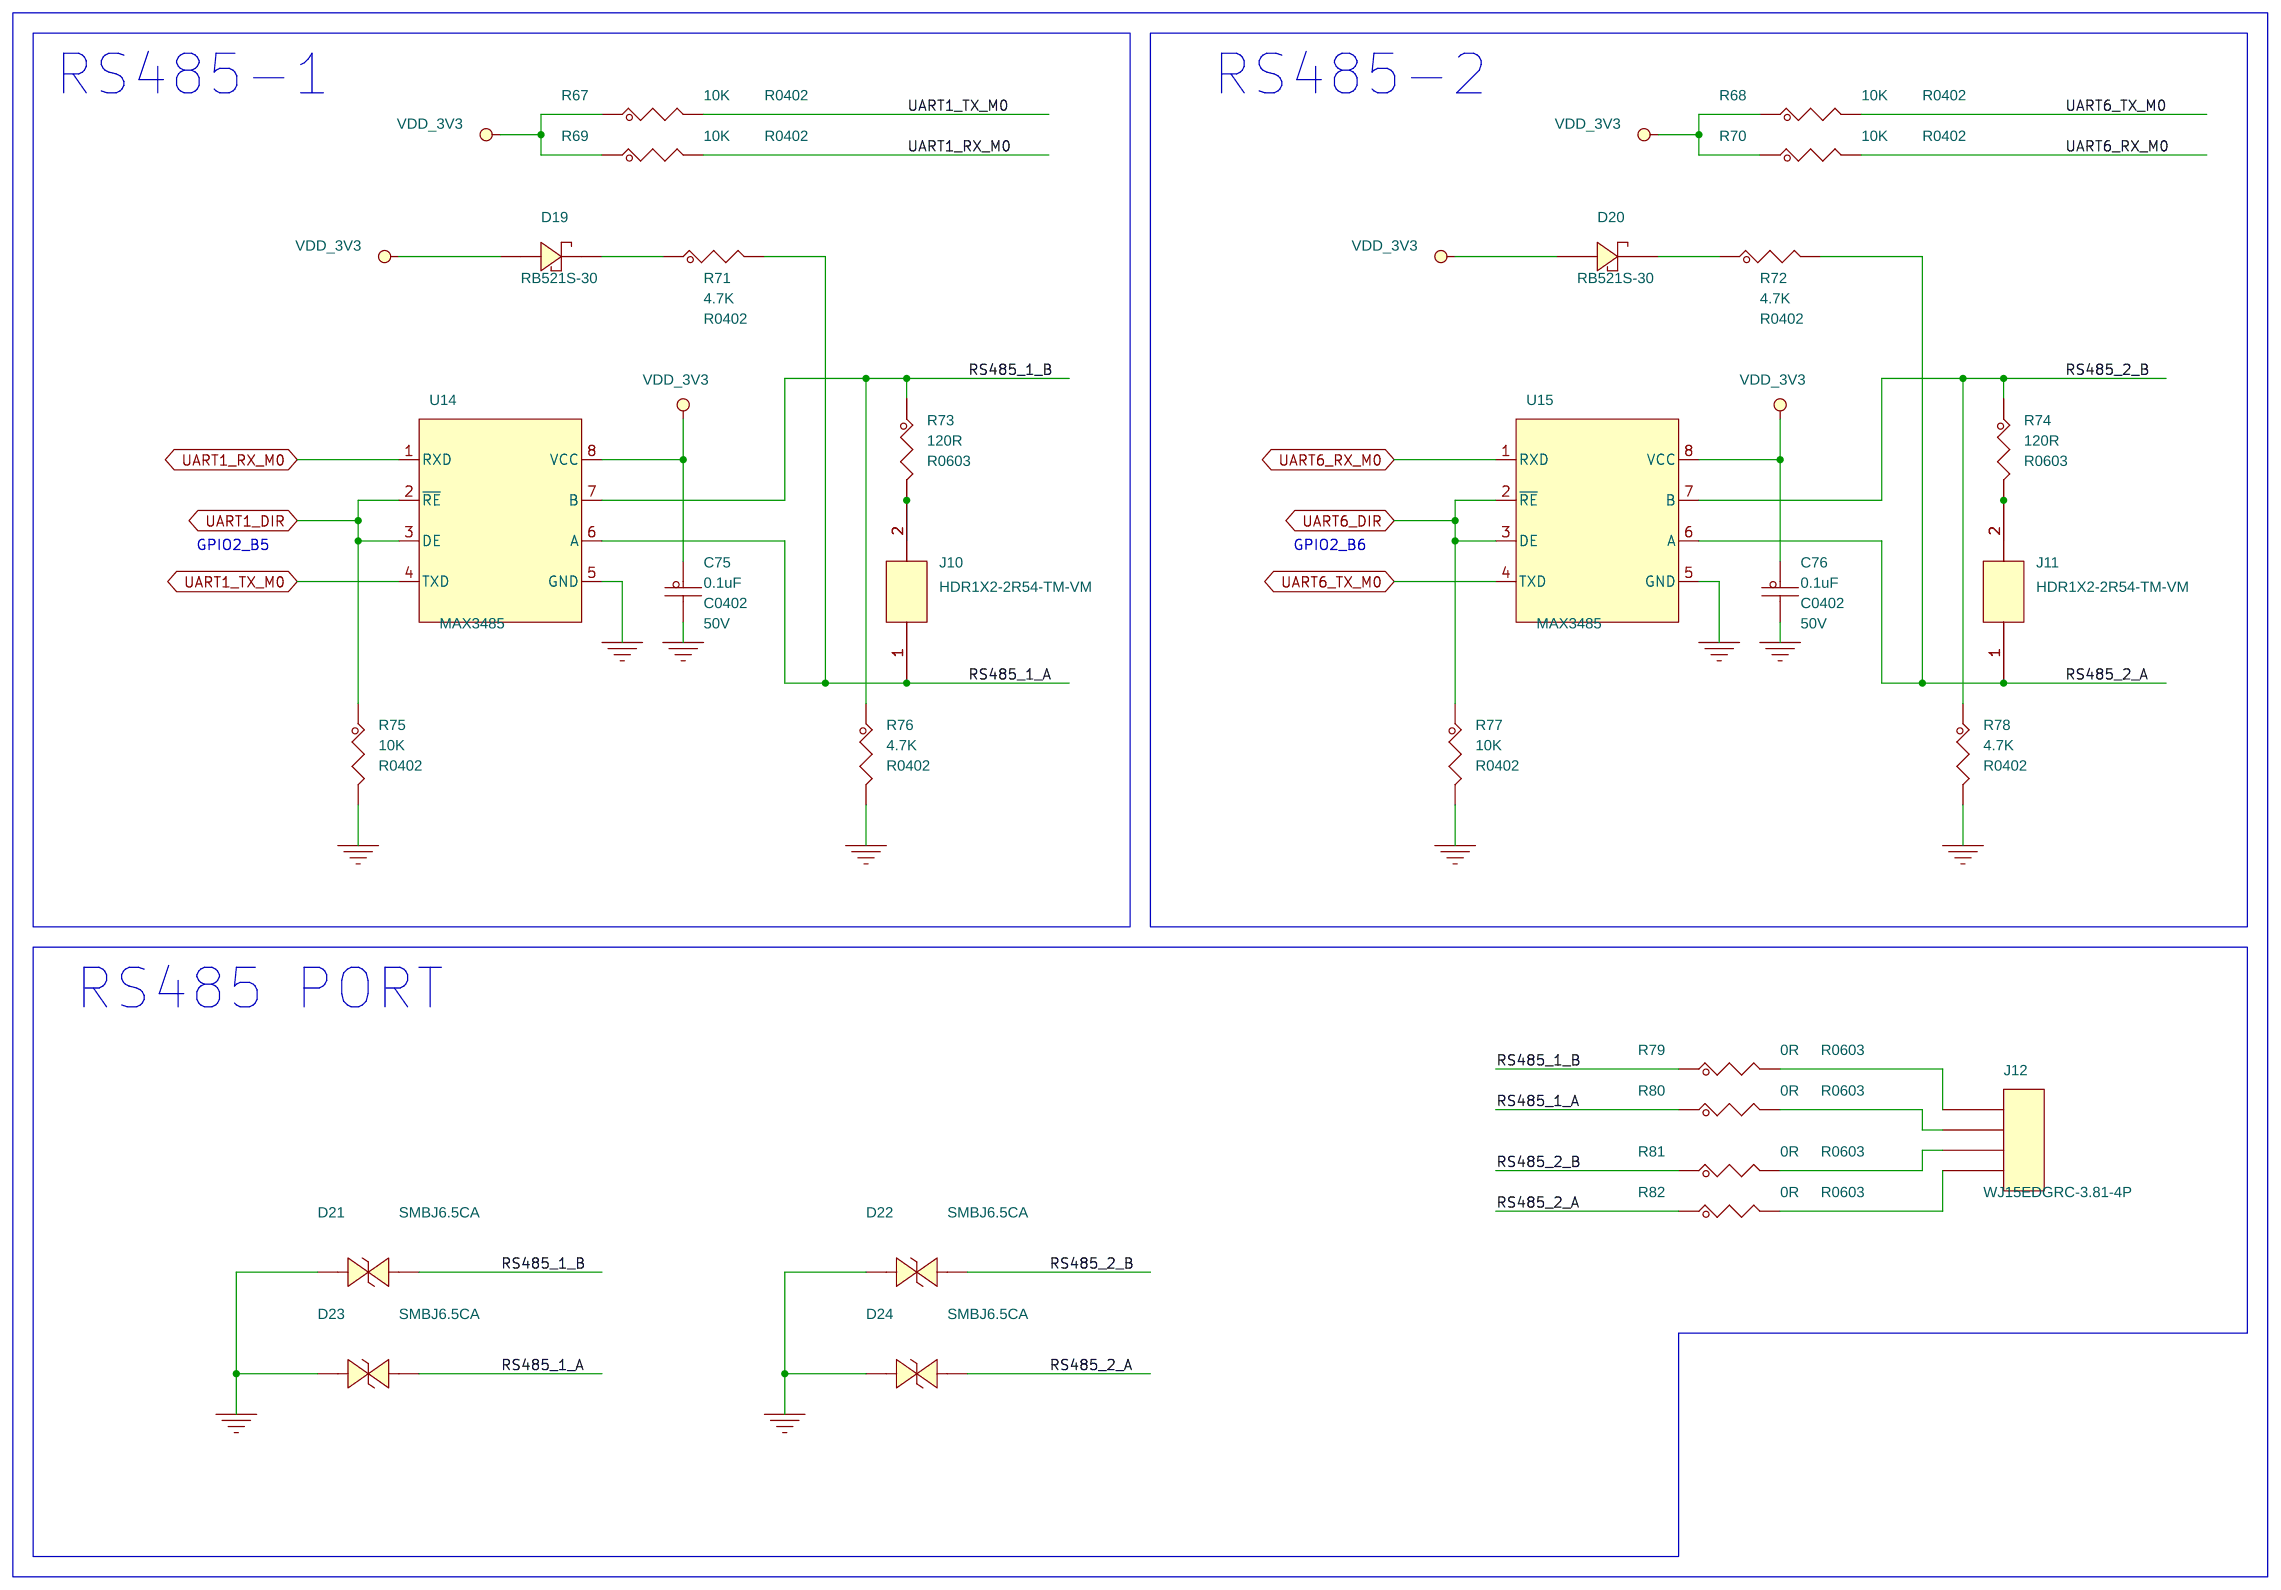
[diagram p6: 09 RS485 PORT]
8 11 ETH: size A3; note: ETH
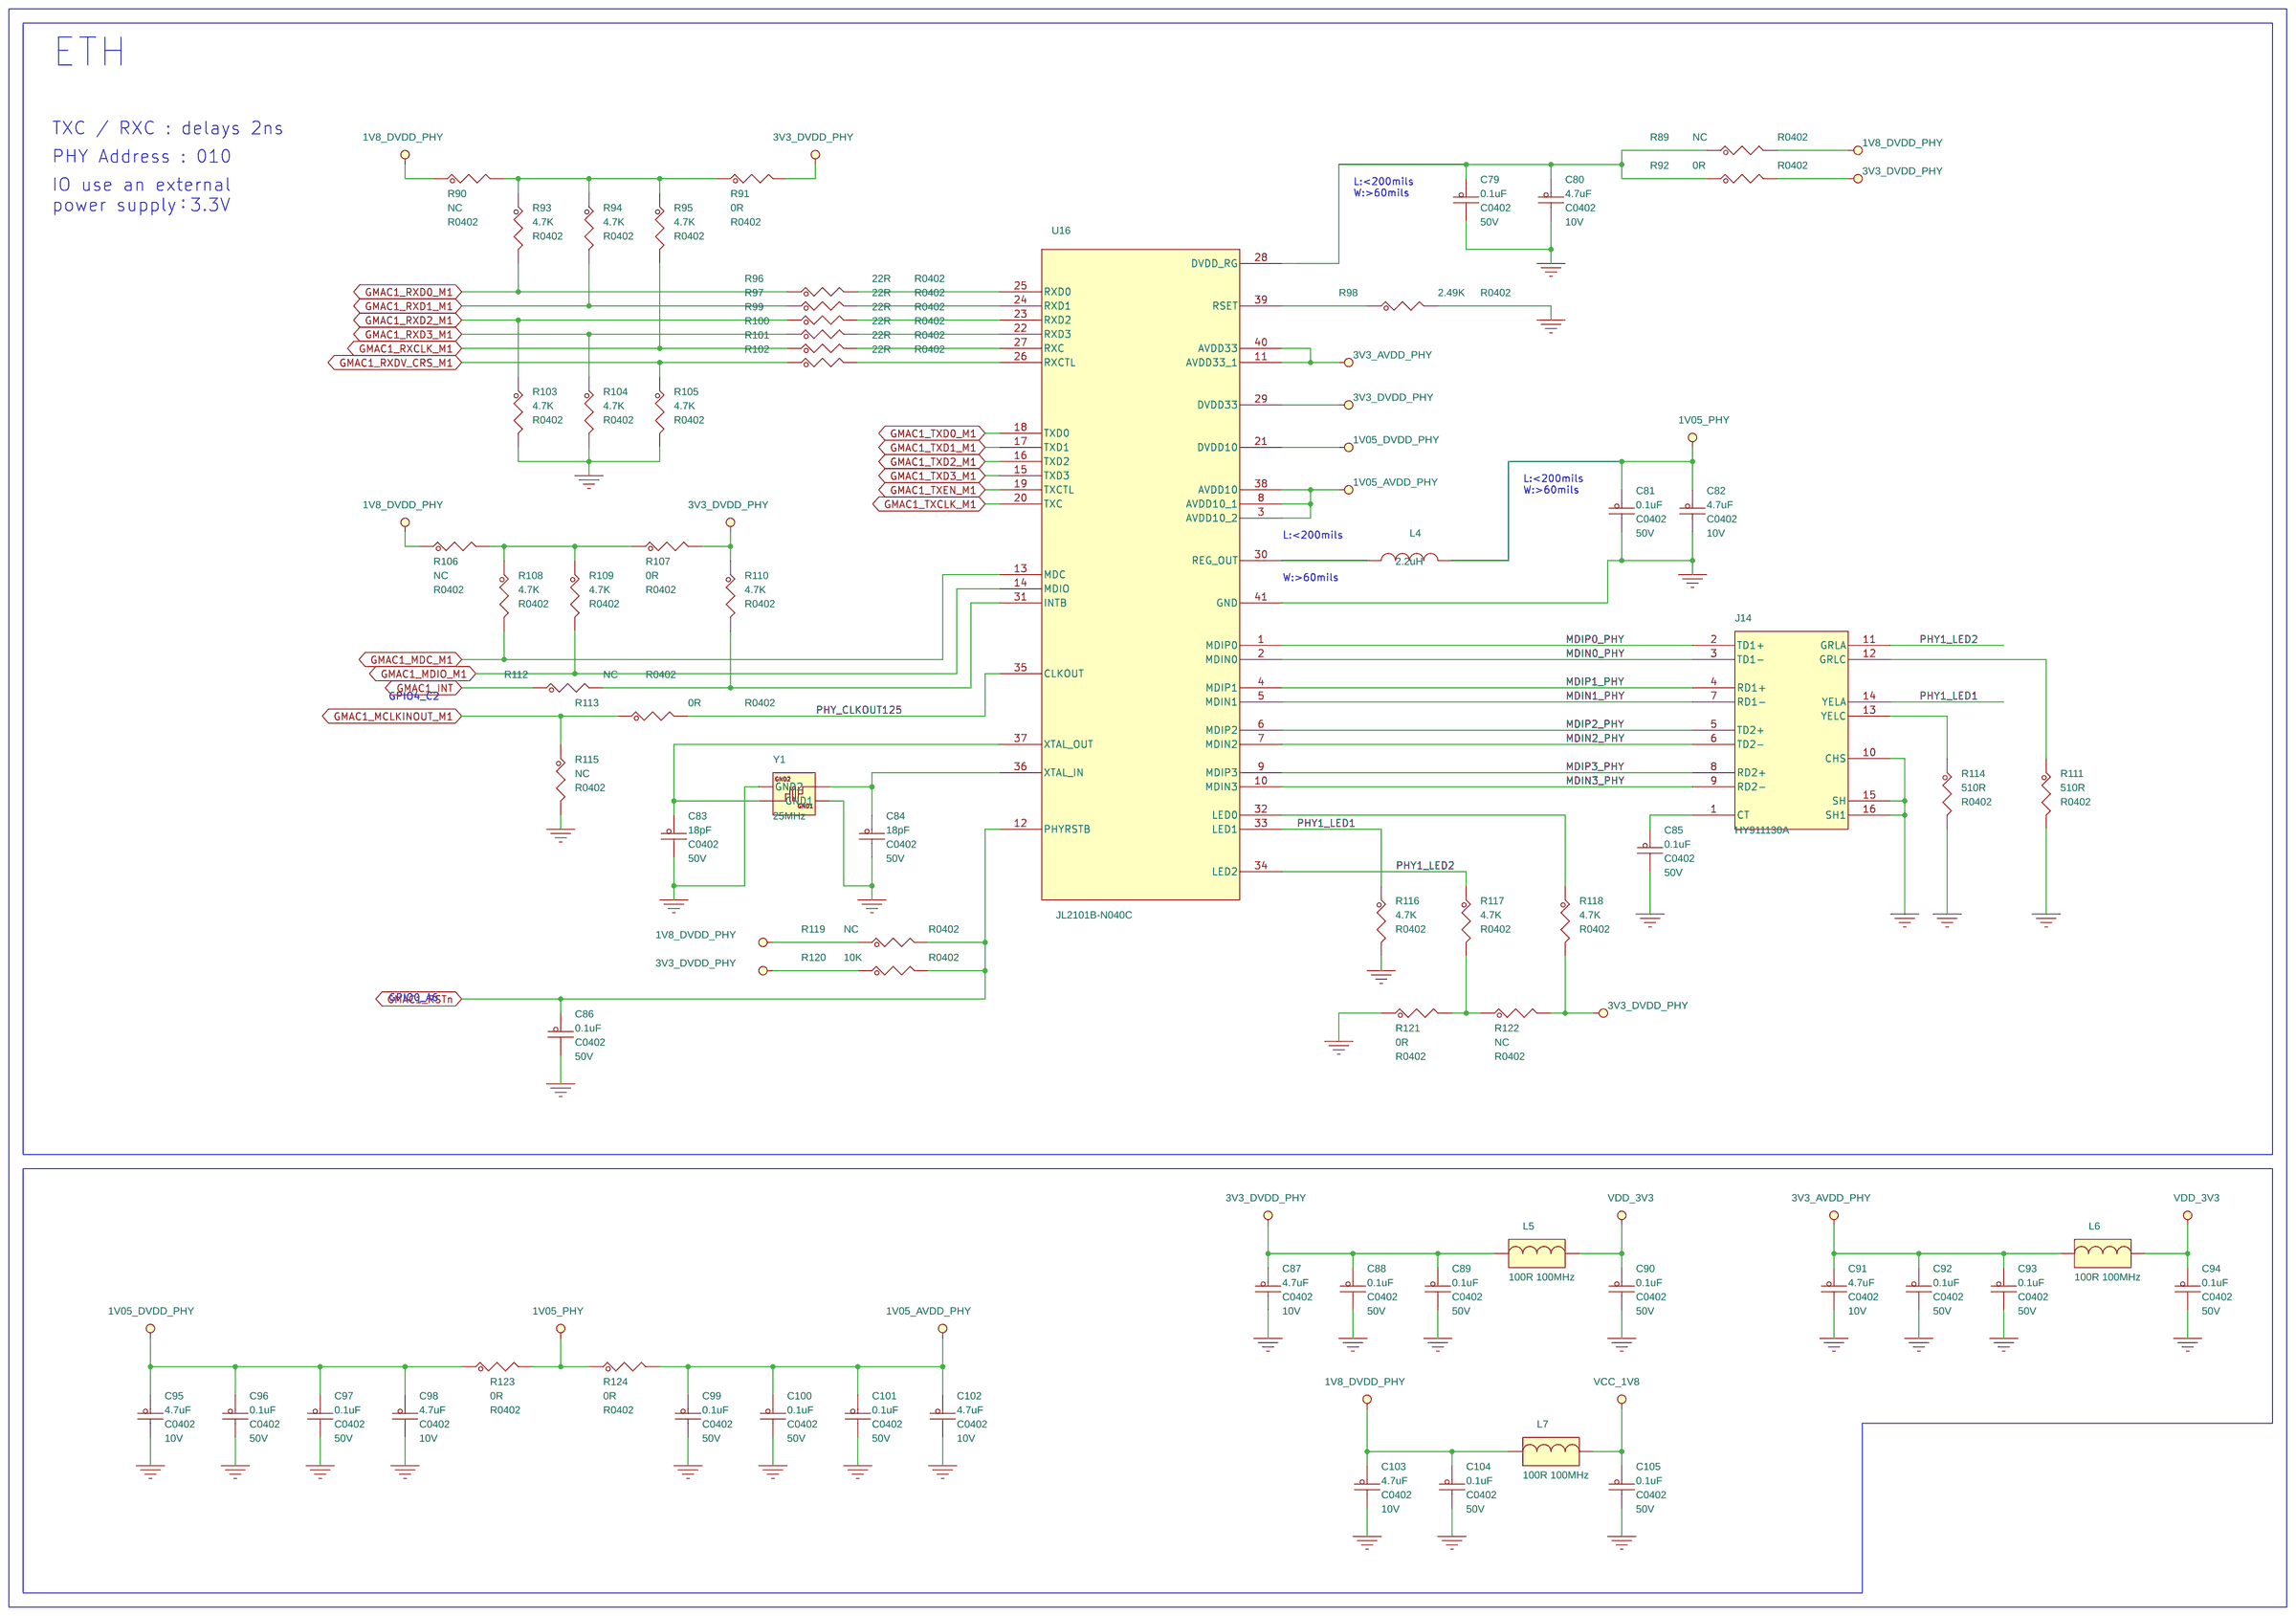
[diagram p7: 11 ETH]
9 13 USB PORT: size A3; note: USB PORT
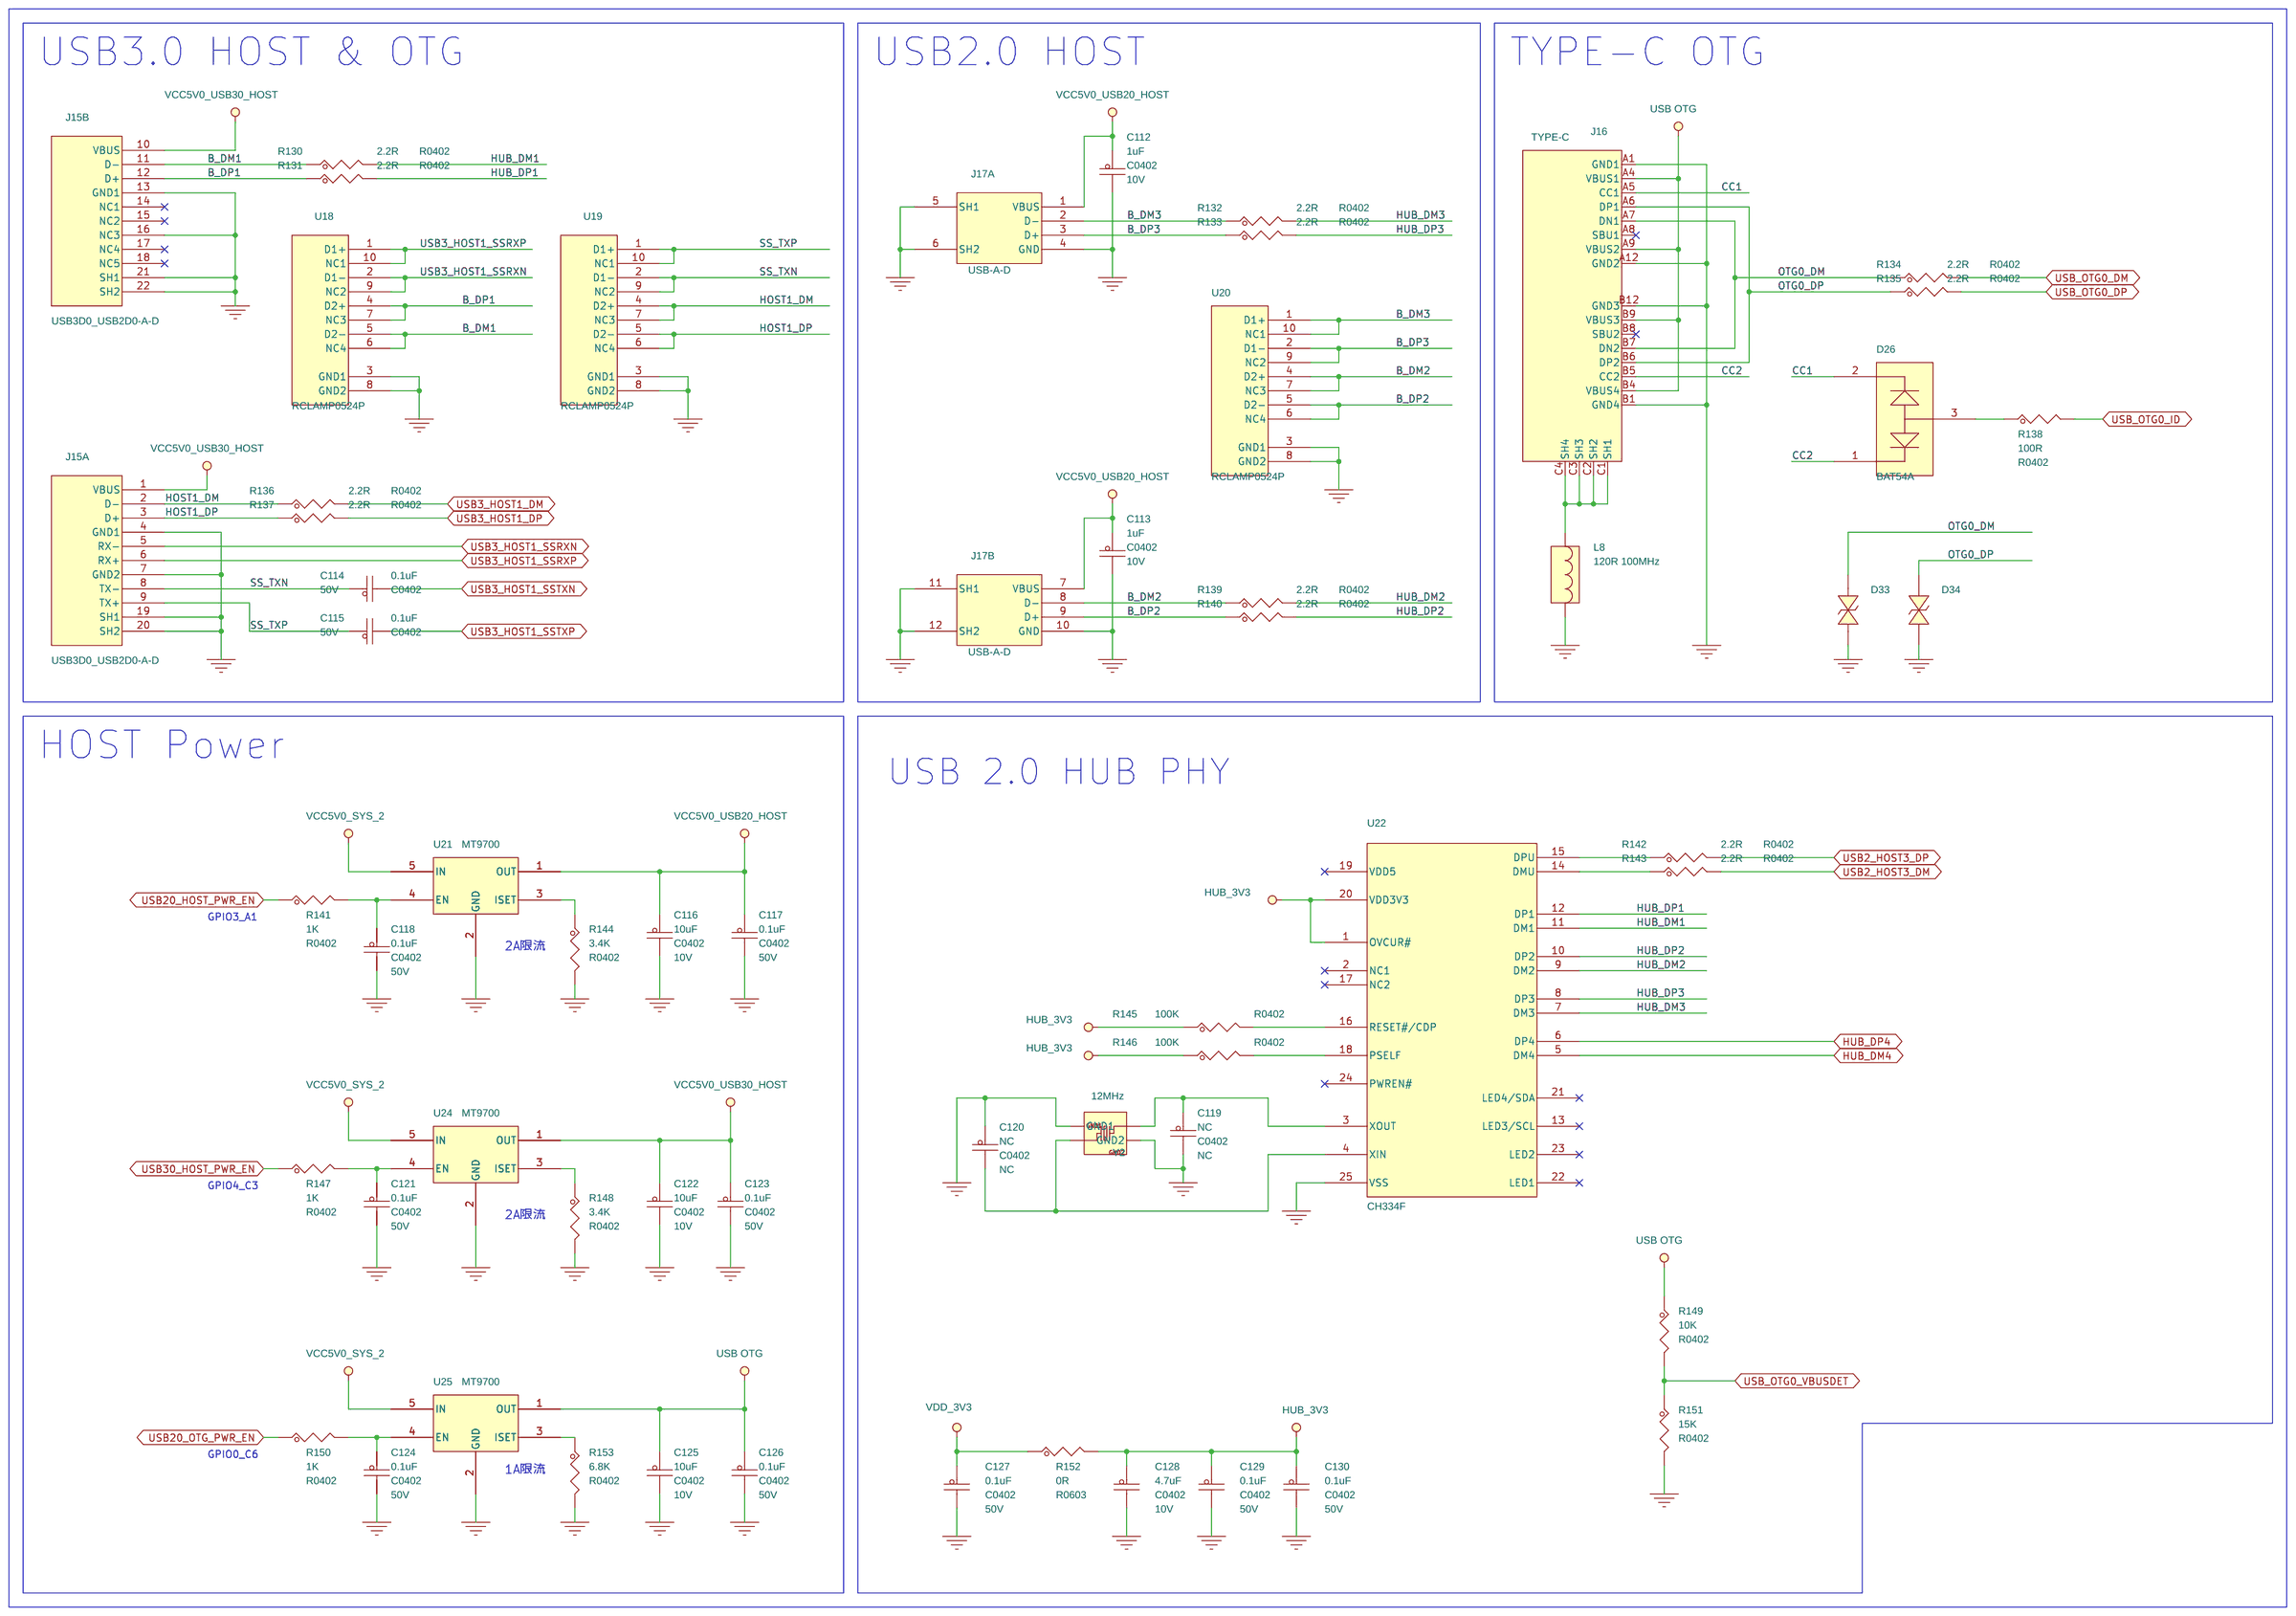
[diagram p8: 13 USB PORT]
10 14 HDMI PORT: size A4; note: HDMI PORT
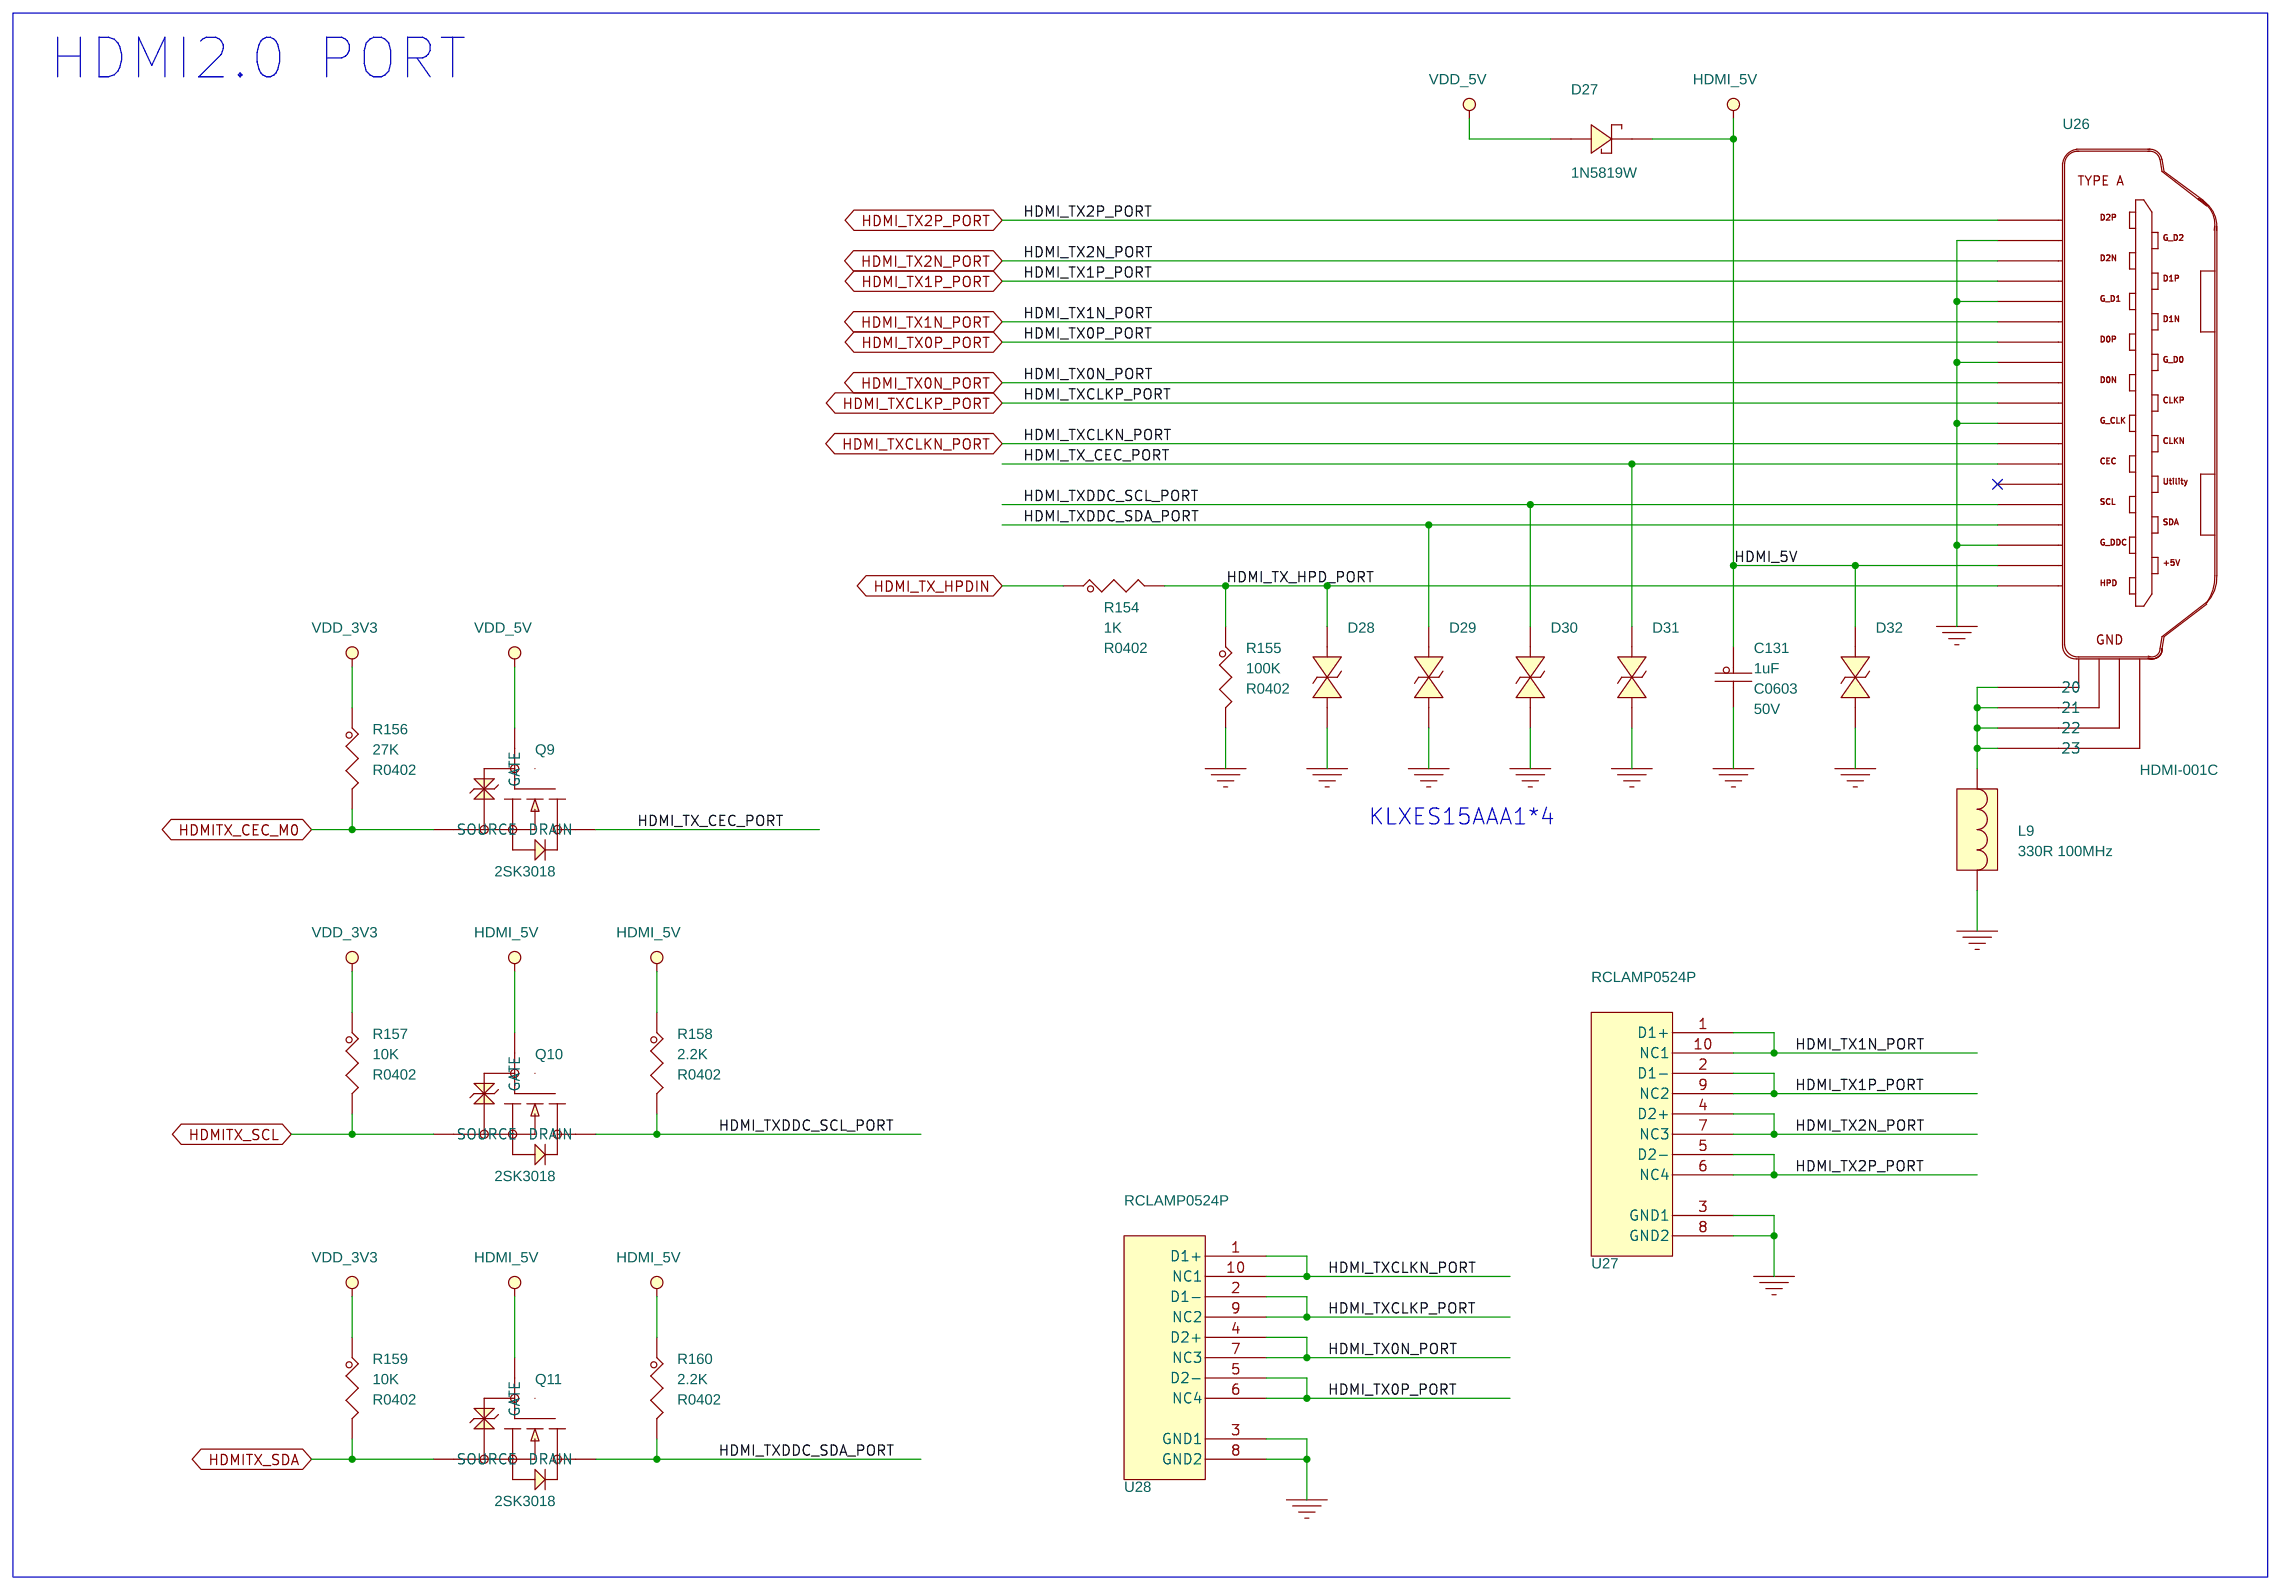
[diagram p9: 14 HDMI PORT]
11 15 MIPI DSI PORT: size A3; note: MIPI DSI PORT
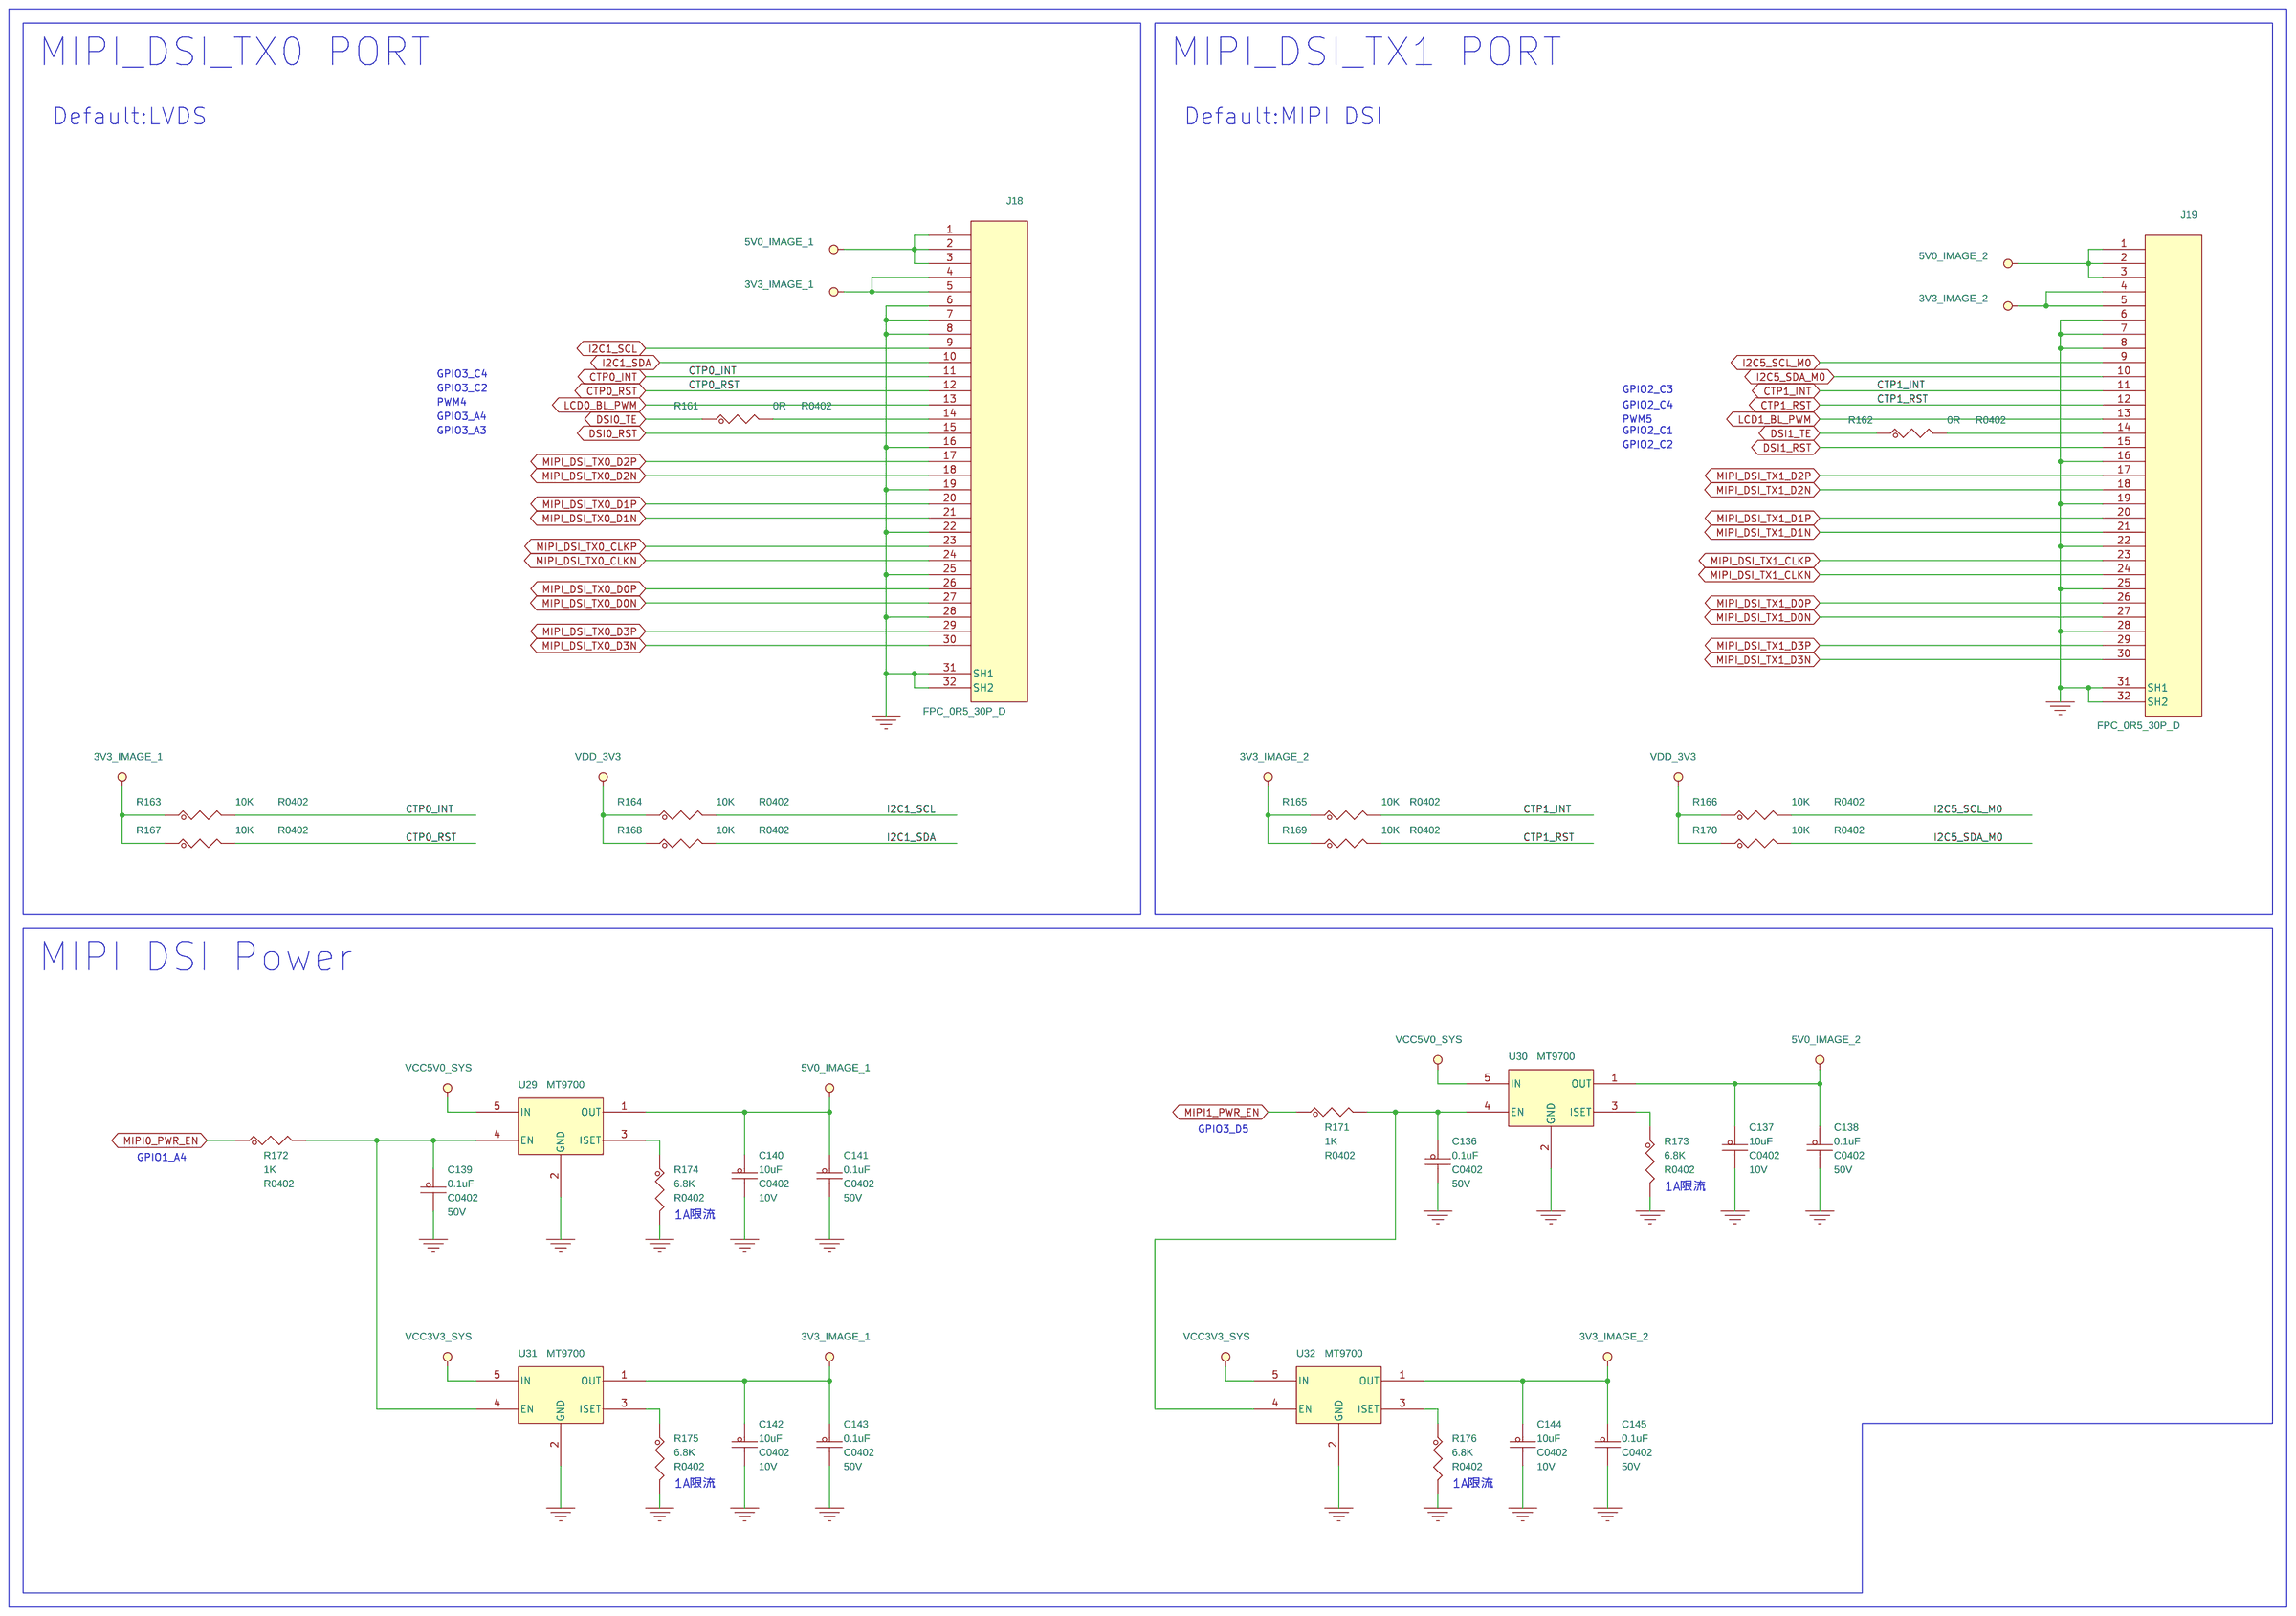
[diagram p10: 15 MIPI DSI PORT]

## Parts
sheet 05 POWER OUT PORT
C38  0.1uF  [C0402]
C39  10uF  [C0603]
C40  0.1uF  [C0402]
C41  0.1uF  [C0402]
C42  10uF  [C0402]
C43  0.1uF  [C0402]
C47  0.1uF  [C0402]
C48  10uF  [C0402]
C49  0.1uF  [C0402]
J3  PH-6A  [PH-1X6-2P0]
Q4  AO3407  [SOT23]
Q5  AO3407  [SOT23]
Q6  SS8050  [SOT23]
R26  0R  [R0603]
R27  20K  [R0402]
R29  510R  [R0402]
R30  10K  [R0402]
R31  1K  [R0402]
R32  6.8K  [R0402]
R33  1K  [R0402]
R34  6.8K  [R0402]
U6  MT9700  [SOT23-5]
U7  MT9700  [SOT23-5]
sheet 06 DDR4 Connector
C50  0.1uF  [C0402]
C51  0.1uF  [C0402]
C52  0.1uF  [C0402]
C53  0.1uF  [C0402]
C54  0.1uF  [C0402]
C55  0.1uF  [C0402]
C56  1uF  [C0402]
J30  AS0A826-H2SB-7H  [AS0A826-H2SB-7H]  (sections A,B)
R35  25.5K  [R0402]
R36  10K  [R0402]
SS5  M2.5X3mm  [SMTSO-M2r5]
SS6  M2.5X3mm  [SMTSO-M2r5]
sheet 09 RS485 PORT
C75  0.1uF  [C0402]
C76  0.1uF  [C0402]
D19  RB521S-30  [SOD523]
D20  RB521S-30  [SOD523]
D21  SMBJ6.5CA  [SMB-CA]
D22  SMBJ6.5CA  [SMB-CA]
D23  SMBJ6.5CA  [SMB-CA]
D24  SMBJ6.5CA  [SMB-CA]
J10  HDR1X2-2R54-TM-VM  [HDR1X2-2R54-TM-VM]
J11  HDR1X2-2R54-TM-VM  [HDR1X2-2R54-TM-VM]
J12  WJ15EDGRC-3.81-4P  [DB2ERC-3P81-4P]
R67  10K  [R0402]
R68  10K  [R0402]
R69  10K  [R0402]
R70  10K  [R0402]
R71  4.7K  [R0402]
R72  4.7K  [R0402]
R73  120R  [R0603]
R74  120R  [R0603]
R75  10K  [R0402]
R76  4.7K  [R0402]
R77  10K  [R0402]
R78  4.7K  [R0402]
R79  0R  [R0603]
R80  0R  [R0603]
R81  0R  [R0603]
R82  0R  [R0603]
U14  MAX3485  [SOP8]
U15  MAX3485  [SOP8]
sheet 11 ETH
C79  0.1uF  [C0402]
C80  4.7uF  [C0402]
C81  0.1uF  [C0402]
C82  4.7uF  [C0402]
C83  18pF  [C0402]
C84  18pF  [C0402]
C85  0.1uF  [C0402]
C86  0.1uF  [C0402]
C87  4.7uF  [C0402]
C88  0.1uF  [C0402]
C89  0.1uF  [C0402]
C90  0.1uF  [C0402]
C91  4.7uF  [C0402]
C92  0.1uF  [C0402]
C93  0.1uF  [C0402]
C94  0.1uF  [C0402]
C95  4.7uF  [C0402]
C96  0.1uF  [C0402]
C97  0.1uF  [C0402]
C98  4.7uF  [C0402]
C99  0.1uF  [C0402]
C100  0.1uF  [C0402]
C101  0.1uF  [C0402]
C102  4.7uF  [C0402]
C103  4.7uF  [C0402]
C104  0.1uF  [C0402]
C105  0.1uF  [C0402]
J14  HY911130A  [HY911130A]
L4  2.2uH  [L2520]
L5  100R 100MHz  [L0603]
L6  100R 100MHz  [L0603]
L7  100R 100MHz  [L0603]
R89  NC  [R0402]
R90  NC  [R0402]
R91  0R  [R0402]
R92  0R  [R0402]
R93  4.7K  [R0402]
R94  4.7K  [R0402]
R95  4.7K  [R0402]
R96  22R  [R0402]
R97  22R  [R0402]
R98  2.49K  [R0402]
R99  22R  [R0402]
R100  22R  [R0402]
R101  22R  [R0402]
R102  22R  [R0402]
R103  4.7K  [R0402]
R104  4.7K  [R0402]
R105  4.7K  [R0402]
R106  NC  [R0402]
R107  0R  [R0402]
R108  4.7K  [R0402]
R109  4.7K  [R0402]
R110  4.7K  [R0402]
R111  510R  [R0402]
R112  NC  [R0402]
R113  0R  [R0402]
R114  510R  [R0402]
R115  NC  [R0402]
R116  4.7K  [R0402]
R117  4.7K  [R0402]
R118  4.7K  [R0402]
R119  NC  [R0402]
R120  10K  [R0402]
R121  0R  [R0402]
R122  NC  [R0402]
R123  0R  [R0402]
R124  0R  [R0402]
U16  JL2101B-N040C  [qfp_40p_r]
Y1  25MHz  [3225]
sheet 12 WLAN BT
C106  10pF  [C0402]
C107  NC  [C0402]
C108  NC  [C0402]
C109  0.1uF  [C0402]
C110  10uF  [C0402]
C111  0.1uF  [C0402]
CN1  WiFi-Ant  [UFL-3]
Q7  AO3407  [SOT23]
R125  2.2R  [R0402]
R126  2.2R  [R0402]
R127  10K  [R0402]
R128  510R  [R0402]
U17  TL8821CUB  [RL-UM02WBS-8723BU]
sheet 13 USB PORT
C112  1uF  [C0402]
C113  1uF  [C0402]
C114  0.1uF  [C0402]
C115  0.1uF  [C0402]
C116  10uF  [C0402]
C117  0.1uF  [C0402]
C118  0.1uF  [C0402]
C119  NC  [C0402]
C120  NC  [C0402]
C121  0.1uF  [C0402]
C122  10uF  [C0402]
C123  0.1uF  [C0402]
C124  0.1uF  [C0402]
C125  10uF  [C0402]
C126  0.1uF  [C0402]
C127  0.1uF  [C0402]
C128  4.7uF  [C0402]
C129  0.1uF  [C0402]
C130  0.1uF  [C0402]
D26  BAT54A  [SOT23]
D33  KLXES15AAA1  [ES0402]
D34  KLXES15AAA1  [ES0402]
J15  USB3D0_USB2D0-A-D  [USB3D0-AF-18P]  (sections A,B)
J16  TYPE-C  [TYPE-C-31-M-12]
J17  USB-A-D  [USB-A-D]  (sections A,B)
L8  120R 100MHz  [L0603]
R130  2.2R  [R0402]
R131  2.2R  [R0402]
R132  2.2R  [R0402]
R133  2.2R  [R0402]
R134  2.2R  [R0402]
R135  2.2R  [R0402]
R136  2.2R  [R0402]
R137  2.2R  [R0402]
R138  100R  [R0402]
R139  2.2R  [R0402]
R140  2.2R  [R0402]
R141  1K  [R0402]
R142  2.2R  [R0402]
R143  2.2R  [R0402]
R144  3.4K  [R0402]
R145  100K  [R0402]
R146  100K  [R0402]
R147  1K  [R0402]
R148  3.4K  [R0402]
R149  10K  [R0402]
R150  1K  [R0402]
R151  15K  [R0402]
R152  0R  [R0603]
R153  6.8K  [R0402]
U18  RCLAMP0524P  [USON_10]
U19  RCLAMP0524P  [USON_10]
U20  RCLAMP0524P  [USON_10]
U21  MT9700  [SOT23-5]
U22  CH334F  [QFN24]
U24  MT9700  [SOT23-5]
U25  MT9700  [SOT23-5]
Y2  12MHz  [3225]
sheet 14 HDMI PORT
C131  1uF  [C0603]
D27  1N5819W  [SOD-123]
D28  KLXES15AAA1  [ES0402]
D29  KLXES15AAA1  [ES0402]
D30  KLXES15AAA1  [ES0402]
D31  KLXES15AAA1  [ES0402]
D32  KLXES15AAA1  [ES0402]
L9  330R 100MHz  [L0603]
Q9  2SK3018  [SOT23]
Q10  2SK3018  [SOT23]
Q11  2SK3018  [SOT23]
R154  1K  [R0402]
R155  100K  [R0402]
R156  27K  [R0402]
R157  10K  [R0402]
R158  2.2K  [R0402]
R159  10K  [R0402]
R160  2.2K  [R0402]
U26  HDMI-001C  [HDMI-SMD]
U27  RCLAMP0524P  [USON_10]
U28  RCLAMP0524P  [USON_10]
sheet 15 MIPI DSI PORT
C136  0.1uF  [C0402]
C137  10uF  [C0402]
C138  0.1uF  [C0402]
C139  0.1uF  [C0402]
C140  10uF  [C0402]
C141  0.1uF  [C0402]
C142  10uF  [C0402]
C143  0.1uF  [C0402]
C144  10uF  [C0402]
C145  0.1uF  [C0402]
J18  FPC_0R5_30P_D  [FPC-30P-0P5]
J19  FPC_0R5_30P_D  [FPC-30P-0P5]
R161  0R  [R0402]
R162  0R  [R0402]
R163  10K  [R0402]
R164  10K  [R0402]
R165  10K  [R0402]
R166  10K  [R0402]
R167  10K  [R0402]
R168  10K  [R0402]
R169  10K  [R0402]
R170  10K  [R0402]
R171  1K  [R0402]
R172  1K  [R0402]
R173  6.8K  [R0402]
R174  6.8K  [R0402]
R175  6.8K  [R0402]
R176  6.8K  [R0402]
U29  MT9700  [SOT23-5]
U30  MT9700  [SOT23-5]
U31  MT9700  [SOT23-5]
U32  MT9700  [SOT23-5]

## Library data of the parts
C38 C40 C41 C43 C47 C49 C75 C76 C79 C81 C85 C86 C88-C90 C92-C94 C96 C97 C99-C101 C104 C105 C114 C115 C117 C118 C121 C123 C124 C126 C127 C129 C130 C136 C138 C139 C141 C143 C145 = CAP_NP: Voltage: 50V; 规格: 贴片电容0.1uF 10% 50V X5R 0402; 规格编号: 0402X104K500NT; 规格书: 风华电容.pdf; 价格: 0.029826; 类别: 贴片电容0402; 品牌: 风华; 生命周期: 量产; 条码: EBF29060118
C39 = CAP_NP: Voltage: 25V; 规格: 贴片电容10uF 20% 25V X5R 0603; 规格编号: CL10A106MA8NRNC; 规格书: 三星电容.pdf; 价格: 0.109811; 类别: 贴片电容0603; 品牌: 三星; 生命周期: 量产; 条码: EBF29060171
C42 C48 C116 C122 C125 C137 C140 C142 C144 = CAP_NP: Voltage: 10V; 规格: 贴片电容10uF 20% 10V X5R 0402; 规格编号: CL05A106MP8NUB8; 规格书: 三星电容.pdf; 价格: 0.518415; 类别: 贴片电容0402; 品牌: 三星; 生命周期: 量产; 条码: EBF29060247
J3 = 1X6PIN: 规格: 直针PH2.0-6P 间距2.0MM 拔插式 接插件; 规格书: 博穆精密_PH2.0-A.pdf; 价格: 0.0228; 可替代料: EBF29020026; 类别: PH连接器; 品牌: 博穆精密; 生命周期: 量产; 条码: EBF29020026
Q4 Q5 Q7 = MOSFET_P: 规格: P沟道MOS 导通电阻60mΩ 电流4.1A 3V可驱动; 规格书: 合科泰-AO3407.pdf; 价格: 0.199827; 类别: P-MOS; 品牌: 合科泰; 生命周期: 量产; 丝印: A7; 条码: EBF29280012
Q6 = NPN: 规格: 贴片三极管SS8050 集电极电流1.5A 额定功率300mW NPN; 规格书: 江苏长电-SS8050Y1.pdf; 价格: 0.086744; 类别: 贴片三极管SOT-23; 品牌: 江苏长电; 生命周期: 量产; 丝印: Y1; 条码: EBF29090001
R26 R79-R82 R152 = RES: 规格: 贴片电阻0R 1% 1/10W 0603; 规格编号: RI0603L0000FT; 规格书: 合科泰-RI系列电阻.pdf; 类别: 贴片电阻0603; 品牌: 合科泰; 生命周期: 量产; 条码: EBF29070063
R27 = RES: 规格: 贴片电阻20K 1% 1/16W 0402; 规格编号: 0402WGF2002TCE; 规格书: 厚声-无铅厚膜电阻.pdf; 价格: 0.002473; 类别: 贴片电阻0402; 品牌: 厚声; 生命周期: 量产; 条码: EBF29070223
R29 R111 R114 R128 = RES: 规格: 贴片电阻510R 1% 1/16W 0402; 规格编号: 0402WGF5100TCE; 规格书: 厚声-无铅厚膜电阻.pdf; 价格: 0.003791; 类别: 贴片电阻0402; 品牌: 厚声; 生命周期: 量产; 条码: EBF29070293
R30 R36 R67-R70 R75 R77 R120 R127 R149 R157 R159 R163-R170 = RES: 规格: 贴片电阻10K 1% 1/16W 0402; 规格编号: 0402WGF1002TCE; 规格书: 厚声-无铅厚膜电阻.pdf; 价格: 0.002773; 类别: 贴片电阻0402; 品牌: 厚声; 生命周期: 量产; 条码: EBF29070046
R31 R33 R141 R147 R150 R154 R171 R172 = RES: 规格: 贴片电阻1K 1% 1/16W 0402; 规格编号: RI0402L1001FT; 规格书: 合科泰-RI系列电阻.pdf; 类别: 贴片电阻0402; 品牌: 合科泰; 生命周期: 量产; 条码: EBF29070050
R32 R34 R153 R173-R176 = RES: 规格: 贴片电阻6.8K 1% 1/16W 0402; 规格编号: RI0402L6801FT; 规格书: 合科泰-RI系列电阻.pdf; 类别: 贴片电阻0402; 品牌: 合科泰; 生命周期: 量产; 条码: EBF29070052
U6 U7 U21 U24 U25 U29-U32 = MT9700: 规格: 负载开关 工作电压2.4V-5.5V 最大电流2A 过流保护; 规格书: MT9700.pdf; 价格: 0.483492; 类别: 功率开关; 品牌: 西安航天民芯; 生命周期: 量产; 丝印: D00HA-X; 条码: EBF29280004
C50-C55 C109 C111 = CAP_NP: voltage: 50V; 规格: 贴片电容0.1uF 10% 50V X5R 0402; 规格编号: 0402X104K500NT; 规格书: 风华电容.pdf; 价格: 0.029826; 类别: 贴片电容0402; 品牌: 风华; 生命周期: 量产; 条码: EBF29060118
C56 C112 C113 = CAP_NP: Voltage: 10V; 规格: 贴片电容1uF 10% 10V X5R 0402; 规格编号: 0402X105K100NT; 规格书: 风华电容.pdf; 价格: 0.01191; 类别: 贴片电容0402; 品牌: 风华; 生命周期: 量产; 条码: EBF29060121
J30 = AS0A826-H2SB-7H: 备注: RK3566金手指底板; 规格: 正装 DDR4连接器 引脚间距：0.5mm 引脚总数：260 安装方式：卧贴 工作温度范围：-55℃~+85℃; 规格书: 富士康_AS0A826-H2SB-7H.pdf; 类别: 金手指连接器; 品牌: 富士康; 生命周期: 量产; 条码: EBFCIS230513143856
R35 = RES: 规格: 贴片电阻25.5K 1% 1/16W 0402; 规格编号: CQ02WGF2552TCE; 规格书: 厚声-无铅厚膜电阻.pdf; 价格: 0.006152; 类别: 贴片电阻0402; 品牌: 厚声; 生命周期: 量产; 条码: EBF29070291
SS5 SS6 = SPACER: 规格: SMT贴片螺母M2.5 台阶高度1.4MM 台阶外径：4.09MM 螺柱长度：3MM; 规格编号: SMTSO2530CTJ; 规格书: 雄和远景_SMTSO2530CTJ.pdf; 类别: 贴片螺母; 品牌: 雄和远景; 生命周期: 量产; 条码: EBFCIS221028102827
D19 D20 = DIODE_SCHTKY: 规格: 直流反向耐压(Vr)：30V 平均整流电流(Io)：200mA 正向压降(Vf)：500mV@200mA 30V@100mA,VF=350mV@10mA; 规格书: 江苏长电_RB521S-30.pdf; 价格: 0.06781; 类别: 贴片肖特基二极管; 品牌: 江苏长电; 生命周期: 量产; 条码: EBFCIS221114153437
D21-D24 = DIODE_BI-DIR_TRIG: 规格: TVS二极管 箝位电压11.2V 击穿电压7.22V 反向关断电压6.5V; 规格书: 君耀电子-SMBJ15CA.pdf; 价格: 0.226009; 类别: 贴片TVS; 品牌: 君耀电子; 生命周期: 量产; 条码: EBF29140023
J10 J11 = 1X2PIN: 规格: 蓝色直插单排排针 总PIN数2 间距2.54mm; 规格编号: HDR1X2-2R54-TM-VM-BLUE; 规格书: 州日_单排针_直插_2P54.pdf; 价格: 0.02; 类别: 直插单排排针; 品牌: 州日; 生命周期: 量产; 条码: EBF29020019
J12 = CON4: 规格: 插拔式接线端子 间距3.81mm 90度弯针 4PIN; 规格书: 康奈克斯电气-绿色端子弯针插座.pdf; 价格: 0.198381; 类别: 绿色插拔式接线端子; 品牌: 康奈克斯电气; 生命周期: 量产; 条码: EBF29040009
R71 R72 R76 R78 R93-R95 R103-R105 R108-R110 R116-R118 = RES: 规格: 贴片电阻4.7K 1% 1/16W 0402; 规格编号: RI0402L4701FT; 规格书: 合科泰-RI系列电阻.pdf; 类别: 贴片电阻0402; 品牌: 合科泰; 生命周期: 量产; 条码: EBF29070047
R73 R74 = RES: 规格: 贴片电阻120R 1% 1/10W 0603; 规格编号: RI0603L1200FT; 规格书: 合科泰-RI系列电阻.pdf; 类别: 贴片电阻0603; 品牌: 合科泰; 生命周期: 量产; 条码: EBF29070067
U14 U15 = TJA1057GT3: 规格: RS-485/RS-422芯片 收发器 允许32个器件连接总线 协议类别RS-485 电源电压3.3V 数据速率10Mbps; 规格编号: MAX3485ED; 规格书: HTC_MAX3485ED.pdf; 价格: 1.31; 类别: RS485/RS422芯片; 品牌: HTC; 生命周期: 量产; 条码: EBF29150034
C80 C82 C87 C91 C95 C98 C102 C103 C128 = CAP_NP: Voltage: 10V; 规格: 贴片电容4.7uF 10% 10V X5R 0402; 规格编号: CC0402KRX5R6BB475; 规格书: 国巨-贴片电容.pdf; 价格: 0.059058; 类别: 贴片电容0402; 品牌: 国巨; 生命周期: 量产; 条码: EBF29060248
C83 C84 = CAP_NP: Voltage: 50V; 规格: 贴片电容18pF 5% 50V C0G 0402; 规格编号: 0402CG180J500NT; 规格书: 风华电容.pdf; 价格: 0.00515; 类别: 贴片电容0402; 品牌: 风华; 生命周期: 量产; 条码: EBF29060235
J14 = HY911130A: 规格: 屏蔽式以太网连接器RJ45 引脚数14 LED灯黄绿 1000M; 规格书: 汉仁_1000M_ HY911130A.pdf; 价格: 11.12; 可替代料: EBF29040053; 类别: 网口; 品牌: 汉仁; 生命周期: 量产; 条码: EBF29040053
L4 = IND: 规格: 功率电感2.2uH 2.2uH ±20% 2.06A 85mΩ; 规格编号: WIP252012P-2R2ML; 规格书: 佳邦_ WIP252012P-2R2ML.pdf; 价格: 0.129914; 类别: 贴片电感2520; 品牌: 佳邦; 生命周期: 量产; 条码: EBFCIS220927171910
L5-L7 = BEAD: 规格: 磁珠100Ω @100MHz 额定电流3A 直流电阻30mΩ; 规格编号: UPZ1608E101-3R0TF; 规格书: 顺络-磁珠.pdf; 价格: 0.021567; 类别: 贴片磁珠0603; 品牌: 顺络; 生命周期: 量产; 条码: EBF29050038
R89 R90 R106 R112 R115 R119 R122 = RES: 规格: 贴片电阻NC 预留; 类别: 贴片电阻0402; 条码: EBF29070087
R91 R92 R107 R113 R121 R123 R124 R161 R162 = RES: 规格: 贴片电阻0R 1% 1/16W 0402; 规格编号: RI0402L000FT; 规格书: 合科泰-RI系列电阻.pdf; 类别: 贴片电阻0402; 品牌: 合科泰; 生命周期: 量产; 条码: EBF29070049
R96 R97 R99-R102 = RES: 规格: 贴片电阻22R 1% 1/16W 0402; 规格编号: RI0402L22R0FT; 规格书: 合科泰-RI系列电阻.pdf; 类别: 贴片电阻0402; 品牌: 合科泰; 生命周期: 量产; 条码: EBF29070181
R98 = RES: 规格: 贴片电阻2.49K 1% 1/16W 0402; 规格编号: 0402WGF2491TCE; 规格书: 厚声-无铅厚膜电阻.pdf; 价格: 0.004709; 类别: 贴片电阻0402; 品牌: 厚声; 生命周期: 量产; 条码: EBF29070292
U16 = RTL8211F: 备注: 旧版芯片的优化升级版本 Pin to Pin芯片; 规格: 以太网芯片 10M/100M/1000M 控制接口：RGMII RGMII电压：3.3V/2.5V/1.8V/1.5V; 规格书: 景略半导体-JL2101-v1.07.pdf; 类别: 以太网芯片; 品牌: 景略半导体; 生命周期: 量产; 条码: EBFCIS230802110114
Y1 = CRYSTAL_4P: 规格: 无源晶振25MHZ 50Ω 16pF 3225; 规格编号: X322525MQB4SI; 规格书: 扬兴科技-25MHZ.pdf; 价格: 0.385846; 类别: 贴片晶振 3225; 品牌: 扬兴科技; 生命周期: 量产; 条码: EBF29100005
C106 = CAP_NP: voltage: 50V; 规格: 贴片电容10pF 5% 50V C0G 0402; 规格编号: 0402CG100J500NT; 规格书: 风华电容.pdf; 价格: 0.00453; 类别: 贴片电容0402; 品牌: 风华; 生命周期: 量产; 条码: EBF29060127
C107 C108 C119 C120 = CAP_NP: 规格: 贴片电容NC 预留; 类别: 贴片电容0402; 条码: EBF29060149
C110 = CAP_NP: voltage: 10V; 规格: 贴片电容10uF 20% 10V X5R 0402; 规格编号: CL05A106MP8NUB8; 规格书: 三星电容.pdf; 价格: 0.518415; 类别: 贴片电容0402; 品牌: 三星; 生命周期: 量产; 条码: EBF29060247
CN1 = WIFI_ANT: 规格: RF同轴连接器（天线座）; 规格编号: KH-IPEX-K501-29; 规格书: 金航标-天线座.pdf; 价格: 0.247224; 类别: WiFi天线座; 品牌: 金航标; 生命周期: 量产; 条码: EBF430005
R125 R126 R130-R137 R139 R140 R142 R143 = RES: 规格: 贴片电阻2.2R 1% 1/16W 0402; 规格编号: 0402WGF220KTCE; 规格书: 厚声-无铅厚膜电阻.pdf; 价格: 0.003072; 类别: 贴片电阻0402; 品牌: 厚声; 生命周期: 量产; 条码: EBF29070280
U17 = RTL8723: 规格: RTL8821 WiFi模块 接口类型：usb 工作电压：3.3V 传输速率：150M+433M 工作频率：2.4G+5.8G 无线标准：802.11AC/B/G/n 有效通信距离：100m; 价格: 17; 类别: WiFi模块; 品牌: 创凌; 生命周期: 量产; 条码: EBF29250002
D26 = BAT54A: 规格: 肖特基二极管 直流反向耐压30V 平均整流电流200mA 正向压降1V@100mA SOT-23; 规格书: 晶导微电子-BAT54S.pdf; 价格: 0.054466; 类别: 贴片肖特基二极管; 品牌: 晶导微电子; 生命周期: 量产; 条码: EBF29140065
D28-D34 = DIODE_BI-DIR_TRIG: 规格: 用于 USB3.0、HDMI 0.5pF、5V、±15kV ESD 保护二极管; 规格书: KLXES15AAA1.pdf; 价格: 0.09719; 类别: 贴片ESD; 品牌: 永裕泰; 生命周期: 量产; 条码: EBF29140063
J15 = USB3D0_USB2D0-A-D: 规格: USB3.0_USB2.0母座; 规格编号: UEA1112C-UHS6-4F; 规格书: UEA1112C-UHS6-4F.pdf; 类别: USB接口; 品牌: 富士康; 生命周期: 量产; 条码: EBF29040092
J16 = TYPE-C-31-M-12: 规格: Type-C母座 16P 贴片 USB-2.0 插座 高清传输接口 4固定插脚 双向; 规格书: TYPE-C-31-M-12母座贴片.pdf; 价格: 1.06; 类别: USB接口; 品牌: 韩国韩容; 生命周期: 量产; 条码: EBF29040004
J17 = USB-A-D: 规格: 双层USB接口 A型接口 90度双排弯插脚 AF母座 焊接式; 规格编号: 907-111A1012D10200; 规格书: 精拓金-双层USB.pdf; 价格: 0.22; 类别: USB接口; 品牌: 精拓金; 生命周期: 量产; 条码: EBF29020027
L8 = BEAD: 规格: 磁珠120Ω @100MHz 额定电流300mA 直流电阻200mΩ; 规格编号: GZ1608D121TF; 规格书: 顺络-磁珠120Ω±25%100MHZ.pdf; 价格: 0.024822; 类别: 贴片磁珠0603; 品牌: 顺络; 生命周期: 量产; 条码: EBF29050009
R138 = RES: 规格: 贴片电阻100R 1% 1/16W 0402; 规格编号: RI0402L1000FT; 规格书: 合科泰-RI系列电阻.pdf; 类别: 贴片电阻0402; 品牌: 合科泰; 生命周期: 量产; 条码: EBF29070053
R144 R148 = RES: 规格: 贴片电阻3.4K 1% 1/16W 0402; 规格编号: RI0402L3401FT; 规格书: 合科泰-RI系列电阻.pdf; 类别: 贴片电阻0402; 品牌: 合科泰; 生命周期: 量产; 条码: EBF29070186
R145 R146 R155 = RES: 规格: 贴片电阻100K 1% 1/16W 0402; 规格编号: RI0402L1003FT; 规格书: 合科泰-RI系列电阻.pdf; 类别: 贴片电阻0402; 品牌: 合科泰; 生命周期: 量产; 条码: EBF29070054
R151 = RES: 规格: 贴片电阻15K 1% 1/16W 0402; 规格编号: RI0402L1502FT; 规格书: 合科泰-RI系列电阻.pdf; 类别: 贴片电阻0402; 品牌: 合科泰; 生命周期: 量产; 条码: EBF29070222
U18-U20 U27 U28 = RCLAMP0524P: 规格: TVS二极管 箝位电压17V 击穿电压8V 反向关断电压5V; 规格书: 台舟-RCLAMP0524P.pdf; 价格: 0.185957; 类别: 贴片TVS; 品牌: 台舟; 生命周期: 量产; 条码: EBF29140046
U22 = CH334F: 规格: USB HUB芯片 工作电压3.3V 5V 协议类别USB2.0 支持高速(480Mbps) 全速(12Mbps)和低速(1.5Mbps)模式; 规格书: 南京沁恒_CH334F.pdf; 价格: 2.09; 类别: USB芯片; 品牌: 南京沁恒; 生命周期: 量产; 条码: EBFCIS221222095807
Y2 = CRYSTAL_4P: 规格: 无源晶振12MHZ 80Ω 20pF 3225; 规格编号: X322512MSB4SI; 规格书: 扬兴科技-贴片晶振.pdf; 价格: 0.327763; 可替代料: EBF29100013; 类别: 贴片晶振 3225; 品牌: 扬兴科技; 生命周期: 量产; 条码: EBF29100013
C131 = CAP_NP: Voltage: 50V; 规格: 贴片电容1uF 10% 50V X7R 0603; 规格编号: 0603B105K500NT; 规格书: 风华电容.pdf; 价格: 0.099678; 类别: 贴片电容0603; 品牌: 风华; 生命周期: 量产; 条码: EBF29060168
D27 = DIODE_SCHTKY: 规格: 肖特基二极管 直流反向耐压40V 平均整流电流1A 正向压降0.6V@1A SOD-123; 规格书: 1N5819W.pdf; 价格: 0.175675; 类别: 贴片肖特基二极管; 品牌: 台湾迪嘉; 生命周期: 量产; 丝印: SL; 条码: EBF29140016
L9 = BEAD: 规格: 磁珠330Ω @100MHz 额定电流1.7A 直流电阻80mΩ; 规格编号: MPZ1608S331ATA00; 规格书: TDK-MPZ1608S331ATA00.pdf; 类别: 贴片磁珠0603; 品牌: TDK; 生命周期: 量产; 条码: EBF29050003
Q9-Q11 = 2SK3018: 规格: N沟道MOS 导通电阻8Ω 电流10mA 0.8V可驱动; 规格书: 长电科技-2SK3018.pdf; 价格: 0.120725; 类别: N-MOS; 品牌: 江苏长电; 生命周期: 量产; 丝印: KN; 条码: EBF29280009
R156 = RES: 规格: 贴片电阻27K 1% 1/16W 0402; 规格编号: AC0402FR-0727KL; 规格书: YAGEO国巨厚膜无铅电阻.pdf; 价格: 0.007054; 类别: 贴片电阻0402; 品牌: 国巨; 生命周期: 量产; 条码: EBF29070003
R158 R160 = RES: 规格: 贴片电阻2.2K 1% 1/16W 0402; 规格编号: RI0402L2201FT; 规格书: 合科泰-RI系列电阻.pdf; 类别: 贴片电阻0402; 品牌: 合科泰; 生命周期: 量产; 条码: EBF29070051
U26 = HDMI-001C: 规格: HDMI立式; 规格书: HDMI-001C.pdf; 类别: HDMI连接器; 品牌: 讯普; 生命周期: 量产; 条码: EBF29040081
J18 J19 = FPC-30P: 规格: FPC连接器 针脚数30 间距0.5mm 高度2.0mm 下接 卧贴 翻盖式; 规格编号: FPC-05F-30PH20; 规格书: FPC-05F-NPH20.pdf; 类别: FPC连接器; 品牌: 讯普; 生命周期: 量产; 条码: EBF29040079

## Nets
1V05_AVDD_PHY: C99.1 C100.1 C101.1 C102.1 R124.2 U16.3(AVDD10_2) U16.8(AVDD10_1) U16.38(AVDD10)
1V05_DVDD_PHY: C95.1 C96.1 C97.1 C98.1 R123.1 U16.21(DVDD10)
1V05_PHY: C81.1 C82.1 L4.2 R123.2 R124.1
1V8_DVDD_PHY: C103.1 C104.1 L7.1 R89.2 R90.1 R106.1 R119.1
3V3_AVDD_PHY: C91.1 C92.1 C93.1 L6.1 U16.11(AVDD33_1) U16.40(AVDD33)
3V3_DVDD_PHY: C87.1 C88.1 C89.1 L5.1 R91.2 R92.2 R107.2 R110.1 R118.2 R120.1 R122.2 U16.29(DVDD33)
3V3_IMAGE_1: C142.1 C143.1 J18.4 J18.5 R163.1 R167.1 U31.1(OUT)
3V3_IMAGE_2: C144.1 C145.1 J19.4 J19.5 R165.1 R169.1 U32.1(OUT)
3V3_OUT: C42.1 C43.1 J3.5 U6.1(OUT)
3V3_WLAN: C110.1 C111.1 Q7.3(DRAIN) U17.8(VCC3V3)
5V0_IMAGE_1: C140.1 C141.1 J18.1 J18.2 J18.3 U29.1(OUT)
5V0_IMAGE_2: C137.1 C138.1 J19.1 J19.2 J19.3 U30.1(OUT)
5V_OUT: C48.1 C49.1 J3.3 U7.1(OUT)
12V_OUT: C39.1 C40.1 J3.1 Q5.3(DRAIN)
GND: C39.2 C40.2 C41.2 C42.2 C43.2 C47.2 C48.2 C49.2 C50.2 C51.2 C52.2 C53.2 C54.2 C55.2 C56.2 C75.2 C76.2 C79.2 C80.2 C81.2 C82.2 C83.2 C84.2 C85.2 C86.2 C87.2 C88.2 C89.2 C90.2 C91.2 C92.2 C93.2 C94.2 C95.2 C96.2 C97.2 C98.2 C99.2 C100.2 C101.2 C102.2 C103.2 C104.2 C105.2 C107.2 C108.2 C110.2 C111.2 C112.2 C113.2 C116.2 C117.2 C118.2 C119.2 C120.1 C121.2 C122.2 C123.2 C124.2 C125.2 C126.2 C127.2 C128.2 C129.2 C130.2 C131.2 C136.2 C137.2 C138.2 C139.2 C140.2 C141.2 C142.2 C143.2 C144.2 C145.2 CN1.2 CN1.3 D21.1 D22.1 D23.1 D24.1 D28.1 D29.1 D30.1 D31.1 D32.1 D33.1 D34.1 J3.2 J3.4 J3.6 J14.10(CHS) J14.15(SH) J14.16(SH1) J15.4(GND1) J15.7(GND2) J15.13(GND1) J15.16(NC3) J15.19(SH1) J15.20(SH2) J15.21(SH1) J15.22(SH2) J16.A1(GND1) J16.A12(GND2) J16.B1(GND4) J16.B12(GND3) J17.4(GND) J17.5(SH1) J17.6(SH2) J17.10(GND) J17.11(SH1) J17.12(SH2) J18.6 J18.7 J18.8 J18.16 J18.19 J18.22 J18.25 J18.28 J18.31(SH1) J18.32(SH2) J19.6 J19.7 J19.8 J19.16 J19.19 J19.22 J19.25 J19.28 J19.31(SH1) J19.32(SH2) J30.1(P1) J30.2(P2) J30.15(P15) J30.38(P38) J30.53(P53) J30.56(P56) J30.60(P60) J30.63(P63) J30.74(P74) J30.77(P77) J30.80(P80) J30.94(P94) J30.102(P102) J30.103(P103) J30.124(P124) J30.125(P125) J30.134(P134) J30.143(P143) J30.144(P144) J30.145(P145) J30.146(P146) J30.157(P157) J30.164(P164) J30.169(P169) J30.179(P179) J30.180(P180) J30.193(P193) J30.198(P198) J30.206(P206) J30.207(P207) J30.220(P220) J30.228(P228) J30.229(P229) J30.234(P234) J30.237(P237) J30.249(P249) J30.250(P250) J30.251(P251) J30.252(P252) J30.253(P253) J30.254(P254) J30.261(SHIELD_1) J30.262(SHIELD_2) L8.2 L9.2 Q6.2(EMITTER) R30.2 R32.2 R34.2 R36.2 R75.2 R76.2 R77.2 R78.2 R98.2 R103.2 R104.2 R105.2 R111.2 R114.2 R115.2 R116.2 R121.1 R144.2 R148.2 R151.2 R153.2 R155.2 R173.2 R174.2 R175.2 R176.2 SS5.1(NC) SS6.1(NC) U6.2(GND) U7.2(GND) U14.5(GND) U15.5(GND) U16.41(GND) U17.1(GND) U17.5(GND) U18.3(GND1) U18.8(GND2) U19.3(GND1) U19.8(GND2) U20.3(GND1) U20.8(GND2) U21.2(GND) U22.25(VSS) U24.2(GND) U25.2(GND) U26.2 U26.5 U26.8 U26.11 U26.17 U27.3(GND1) U27.8(GND2) U28.3(GND1) U28.8(GND2) U29.2(GND) U30.2(GND) U31.2(GND) U32.2(GND) Y1.2(GND1) Y1.4(GND2) Y2.2(GND1) Y2.4(GND2) ; also on sheet 12 13 14 15 16 17 18 19
VCC3V3_SD: C54.1 J30.243(P243) J30.244(P244) ; also on sheet 15
VCC3V3_SYS: U6.5(IN) U31.5(IN) U32.5(IN) ; also on sheet 17 18
VCC5V0_SYS: C50.1 C51.1 J30.255(P255) J30.256(P256) J30.257(P257) J30.258(P258) J30.259(P259) J30.260(P260) U29.5(IN) U30.5(IN) ; also on sheet 12 17
VCC5V0_SYS_2: U7.5(IN) U21.5(IN) U24.5(IN) U25.5(IN) ; also on sheet 17
VCC5V0_USB20_HOST: C112.1 C113.1 C116.1 C117.1 J17.1(VBUS) J17.7(VBUS) U21.1(OUT)
VCC5V0_USB30_HOST: C122.1 C123.1 J15.1(VBUS) J15.10(VBUS) U24.1(OUT)
VCC_1V8: C52.1 C105.1 J30.245(P245) J30.246(P246) L7.2 ; also on sheet 19
VCC_12V: C38.1 Q4.3(DRAIN) R27.1 ; also on sheet 13 17 18
VCC_RTC: J30.247(P247) J30.248(P248) ; also on sheet 15
VCCA_1V8: C53.1 J30.239(P239) J30.240(P240) R35.1 ; also on sheet 19
VCCIO_ACODEC: C55.1 J30.241(P241) J30.242(P242) ; also on sheet 14
VDD_3V3: C75.1 C76.1 C90.1 C94.1 C109.1 C127.1 D19.2 D20.2 L5.2 L6.2 Q7.2(SOURCE) R67.1 R68.1 R69.1 R70.1 R127.1 R152.1 R156.1 R157.1 R159.1 R164.1 R166.1 R168.1 R170.1 U14.8(VCC) U15.8(VCC) ; also on sheet 15 16 17 19
VDD_5V: D27.2 Q9.1(GATE) ; also on sheet 17
B_DM1: J15.11(D-) R130.1 U18.5(D2-) U18.6(NC4)
B_DM2: J17.8(D-) R139.1 U20.4(D2+) U20.7(NC3)
B_DM3: J17.2(D-) R132.1 U20.1(D1+) U20.10(NC1)
B_DP1: J15.12(D+) R131.1 U18.4(D2+) U18.7(NC3)
B_DP2: J17.9(D+) R140.1 U20.5(D2-) U20.6(NC4)
B_DP3: J17.3(D+) R133.1 U20.2(D1-) U20.9(NC2)
BD_CH3: C56.1 J30.204(P204) R35.2 R36.1
CAM0_nRST: J30.25(P25) ; also on sheet 12
CAM0_PWDN: J30.26(P26) ; also on sheet 12
CAM0_PWR_EN: J30.6(P6) ; also on sheet 12
CAM1_nRST: J30.23(P23) ; also on sheet 12
CAM1_PWDN: J30.16(P16) ; also on sheet 12
CAM1_PWR_EN: J30.49(P49) ; also on sheet 12
CC1: D26.2 J16.A5(CC1)
CC2: D26.1 J16.B5(CC2)
CTP0_INT: J18.11 J30.30(P30) R163.2
CTP0_RST: J18.12 J30.34(P34) R167.2
CTP1_INT: J19.11 J30.33(P33) R165.2
CTP1_RST: J19.12 J30.31(P31) R169.2
DSI0_RST: J18.15 J30.24(P24)
DSI0_TE: J30.22(P22) R161.1
DSI1_RST: J19.15 J30.35(P35)
DSI1_TE: J30.37(P37) R162.1
EDP_BL_EN: J30.136(P136) ; also on sheet 18
EDP_BL_PWM: J30.167(P167) ; also on sheet 18
EDP_HPDIN_M0: J30.45(P45) ; also on sheet 18
EDP_PWR_EN: J30.8(P8) ; also on sheet 18
EDP_TP_INT: J30.12(P12) ; also on sheet 18
EDP_TP_RESET: J30.14(P14) ; also on sheet 18
EDP_TX_AUXN: J30.209(P209) ; also on sheet 18
EDP_TX_AUXP: J30.211(P211) ; also on sheet 18
EDP_TX_D0N: J30.225(P225) ; also on sheet 18
EDP_TX_D0P: J30.227(P227) ; also on sheet 18
EDP_TX_D1N: J30.221(P221) ; also on sheet 18
EDP_TX_D1P: J30.223(P223) ; also on sheet 18
EXT_PWR_EN: J30.231(P231) ; also on sheet 17
FSPI_CLK: J30.218(P218) ; also on sheet 19
FSPI_CS0n: J30.208(P208) ; also on sheet 19
FSPI_D0: J30.210(P210) ; also on sheet 19
FSPI_D1: J30.212(P212) ; also on sheet 19
FSPI_D2: J30.214(P214) ; also on sheet 19
FSPI_D3: J30.216(P216) ; also on sheet 19
GMAC1_INT: J30.43(P43) R112.1
GMAC1_MCLKINOUT_M1: J30.58(P58) R113.1 R115.1
GMAC1_MDC_M1: J30.78(P78) R108.2 U16.13(MDC)
GMAC1_MDIO_M1: J30.76(P76) R109.2 U16.14(MDIO)
GMAC1_RSTn: C86.1 J30.155(P155) R119.2 R120.2 U16.12(PHYRSTB)
GMAC1_RXCLK_M1: J30.82(P82) R95.2 R101.1
GMAC1_RXD0_M1: J30.86(P86) R93.2 R96.1
GMAC1_RXD1_M1: J30.88(P88) R94.2 R97.1
GMAC1_RXD2_M1: J30.90(P90) R99.1 R103.1
GMAC1_RXD3_M1: J30.92(P92) R100.1 R104.1
GMAC1_RXDV_CRS_M1: J30.84(P84) R102.1 R105.1
GMAC1_TXCLK_M1: J30.64(P64) U16.20(TXC)
GMAC1_TXD0_M1: J30.72(P72) U16.18(TXD0)
GMAC1_TXD1_M1: J30.70(P70) U16.17(TXD1)
GMAC1_TXD2_M1: J30.68(P68) U16.16(TXD2)
GMAC1_TXD3_M1: J30.66(P66) U16.15(TXD3)
GMAC1_TXEN_M1: J30.62(P62) U16.19(TXCTL)
GPIO2_B7: J30.17(P17) ; also on sheet 19
GPIO2_C0: J30.39(P39) ; also on sheet 19
HDMI_5V: C131.1 D27.1 D32.2 Q10.1(GATE) Q11.1(GATE) R158.1 R160.1 U26.18
HDMI_TX0N_PORT: J30.131(P131) U26.9 U28.4(D2+) U28.7(NC3)
HDMI_TX0P_PORT: J30.133(P133) U26.7 U28.5(D2-) U28.6(NC4)
HDMI_TX1N_PORT: J30.135(P135) U26.6 U27.1(D1+) U27.10(NC1)
HDMI_TX1P_PORT: J30.137(P137) U26.4 U27.2(D1-) U27.9(NC2)
HDMI_TX2N_PORT: J30.139(P139) U26.3 U27.4(D2+) U27.7(NC3)
HDMI_TX2P_PORT: J30.141(P141) U26.1 U27.5(D2-) U27.6(NC4)
HDMI_TX_CEC_PORT: D31.2 Q9.3(DRAIN) U26.13
HDMI_TX_HPD_PORT: D28.2 R154.2 R155.1 U26.19
HDMI_TX_HPDIN: J30.126(P126) R154.1
HDMI_TXCLKN_PORT: J30.127(P127) U26.12 U28.1(D1+) U28.10(NC1)
HDMI_TXCLKP_PORT: J30.129(P129) U26.10 U28.2(D1-) U28.9(NC2)
HDMI_TXDDC_SCL_PORT: D30.2 Q10.3(DRAIN) R158.2 U26.15
HDMI_TXDDC_SDA_PORT: D29.2 Q11.3(DRAIN) R160.2 U26.16
HDMITX_CEC_M0: J30.128(P128) Q9.2(SOURCE) R156.2
HDMITX_SCL: J30.132(P132) Q10.2(SOURCE) R157.2
HDMITX_SDA: J30.130(P130) Q11.2(SOURCE) R159.2
HOST1_DM: J15.2(D-) R136.1 U19.4(D2+) U19.7(NC3)
HOST1_DP: J15.3(D+) R137.1 U19.5(D2-) U19.6(NC4)
HP_DET_L: J30.4(P4) ; also on sheet 14
HP_SNS: J30.224(P224) ; also on sheet 14
HPL_OUT: J30.226(P226) ; also on sheet 14
HPR_OUT: J30.222(P222) ; also on sheet 14
HUB_3V3: C128.1 C129.1 C130.1 R145.1 R146.1 R152.2 U22.1(OVCUR#) U22.20(VDD3V3)
HUB_DM1: R130.2 U22.11(DM1)
HUB_DM2: R139.2 U22.9(DM2)
HUB_DM3: R132.2 U22.7(DM3)
HUB_DM4: U22.5(DM4) ; also on sheet 13
HUB_DP1: R131.2 U22.12(DP1)
HUB_DP2: R140.2 U22.10(DP2)
HUB_DP3: R133.2 U22.8(DP3)
HUB_DP4: U22.6(DP4) ; also on sheet 13
I2C0_SCL_PMIC: J30.154(P154) ; also on sheet 15
I2C0_SDA_PMIC: J30.152(P152) ; also on sheet 15
I2C1_SCL: J18.9 J30.150(P150) R164.2 ; also on sheet 12
I2C1_SDA: J18.10 J30.148(P148) R168.2 ; also on sheet 12
I2C2_SCL_M1: J30.55(P55) ; also on sheet 16
I2C2_SDA_M1: J30.61(P61) ; also on sheet 16
I2C3_SCL_M0: J30.46(P46) ; also on sheet 16
I2C3_SDA_M0: J30.44(P44) ; also on sheet 16
I2C4_SCL_M0: J30.57(P57) ; also on sheet 18
I2C4_SDA_M0: J30.59(P59) ; also on sheet 18
I2C5_SCL_M0: J19.9 J30.42(P42) R166.2 ; also on sheet 12
I2C5_SDA_M0: J19.10 J30.40(P40) R170.2 ; also on sheet 12
LCD0_BL_PWM: J18.13 J30.163(P163)
LCD1_BL_PWM: J19.13 J30.161(P161)
MDIN0_PHY: J14.3(TD1-) U16.2(MDIN0)
MDIN1_PHY: J14.7(RD1-) U16.5(MDIN1)
MDIN2_PHY: J14.6(TD2-) U16.7(MDIN2)
MDIN3_PHY: J14.9(RD2-) U16.10(MDIN3)
MDIP0_PHY: J14.2(TD1+) U16.1(MDIP0)
MDIP1_PHY: J14.4(RD1+) U16.4(MDIP1)
MDIP2_PHY: J14.5(TD2+) U16.6(MDIP2)
MDIP3_PHY: J14.8(RD2+) U16.9(MDIP3)
MIC_INN: J30.232(P232) ; also on sheet 14
MIC_INP: J30.230(P230) ; also on sheet 14
MINIPCIE_nWDISABLE: J30.173(P173) ; also on sheet 13
MIPI0_PWR_EN: J30.10(P10) R172.1
MIPI1_PWR_EN: J30.47(P47) R171.1
MIPI_CSI_RX_CLK0N: J30.83(P83) ; also on sheet 12
MIPI_CSI_RX_CLK0P: J30.85(P85) ; also on sheet 12
MIPI_CSI_RX_CLK1N: J30.79(P79) ; also on sheet 12
MIPI_CSI_RX_CLK1P: J30.81(P81) ; also on sheet 12
MIPI_CSI_RX_D0N: J30.99(P99) ; also on sheet 12
MIPI_CSI_RX_D0P: J30.101(P101) ; also on sheet 12
MIPI_CSI_RX_D1N: J30.95(P95) ; also on sheet 12
MIPI_CSI_RX_D1P: J30.97(P97) ; also on sheet 12
MIPI_CSI_RX_D2N: J30.91(P91) ; also on sheet 12
MIPI_CSI_RX_D2P: J30.93(P93) ; also on sheet 12
MIPI_CSI_RX_D3N: J30.87(P87) ; also on sheet 12
MIPI_CSI_RX_D3P: J30.89(P89) ; also on sheet 12
MIPI_DSI_TX0_CLKN: J18.24 J30.121(P121)
MIPI_DSI_TX0_CLKP: J18.23 J30.123(P123)
MIPI_DSI_TX0_D0N: J18.27 J30.117(P117)
MIPI_DSI_TX0_D0P: J18.26 J30.119(P119)
MIPI_DSI_TX0_D1N: J18.21 J30.113(P113)
MIPI_DSI_TX0_D1P: J18.20 J30.115(P115)
MIPI_DSI_TX0_D2N: J18.18 J30.109(P109)
MIPI_DSI_TX0_D2P: J18.17 J30.111(P111)
MIPI_DSI_TX0_D3N: J18.30 J30.105(P105)
MIPI_DSI_TX0_D3P: J18.29 J30.107(P107)
MIPI_DSI_TX1_CLKN: J19.24 J30.120(P120)
MIPI_DSI_TX1_CLKP: J19.23 J30.122(P122)
MIPI_DSI_TX1_D0N: J19.27 J30.116(P116)
MIPI_DSI_TX1_D0P: J19.26 J30.118(P118)
MIPI_DSI_TX1_D1N: J19.21 J30.114(P114)
MIPI_DSI_TX1_D1P: J19.20 J30.112(P112)
MIPI_DSI_TX1_D2N: J19.18 J30.108(P108)
MIPI_DSI_TX1_D2P: J19.17 J30.110(P110)
MIPI_DSI_TX1_D3N: J19.30 J30.104(P104)
MIPI_DSI_TX1_D3P: J19.29 J30.106(P106)
OTG0_DM: D33.2 J16.A7(DN1) J16.B7(DN2) R134.1
OTG0_DP: D34.2 J16.A6(DP1) J16.B6(DP2) R135.1
PCIE20_CLKREQn_M0: J30.177(P177) ; also on sheet 13
PCIE20_PERSTn_M0: J30.175(P175) ; also on sheet 13
PCIE20_REFCLKN: J30.181(P181) ; also on sheet 13
PCIE20_REFCLKP: J30.183(P183) ; also on sheet 13
PCIE20_RXN: J30.187(P187) ; also on sheet 13
PCIE20_RXP: J30.185(P185) ; also on sheet 13
PCIE20_TXN: J30.189(P189) ; also on sheet 13
PCIE20_TXP: J30.191(P191) ; also on sheet 13
PCIE20_WAKEn_M0: J30.171(P171) ; also on sheet 13
PCIE_PWREN_EN: J30.149(P149) ; also on sheet 13
PHY1_LED1: J14.14(YELA) R116.1 U16.33(LED1)
PHY1_LED2: J14.11(GRLA) R117.1 U16.34(LED2)
PHY_CLKOUT125: R113.2 U16.35(CLKOUT)
PWM2_M0: J30.159(P159) ; also on sheet 17
PWM3_IR: J30.165(P165) ; also on sheet 19
PWR_3V3_EN: J30.36(P36) R31.1
PWR_5V_EN: J30.140(P140) R33.1
PWR_12V_EN: J30.147(P147) R29.1
PWRON_KEY: J30.235(P235) ; also on sheet 19
RECOVERY: J30.202(P202) ; also on sheet 19
RESET_KEY: J30.233(P233) ; also on sheet 19
RS485_1_A: D23.2 J10.1 R71.2 R80.1 U14.6(A)
RS485_1_B: D21.2 R73.1 R76.1 R79.1 U14.7(B)
RS485_2_A: D24.2 J11.1 R72.2 R82.1 U15.6(A)
RS485_2_B: D22.2 R74.1 R78.1 R81.1 U15.7(B)
RX8010_nIRQ1: J30.20(P20) ; also on sheet 15
RX8010_nIRQ2: J30.18(P18) ; also on sheet 15
SARADC_VIN1: J30.200(P200) ; also on sheet 19
SDMMC0_CLK: J30.178(P178) ; also on sheet 15
SDMMC0_CMD: J30.176(P176) ; also on sheet 15
SDMMC0_D0: J30.174(P174) ; also on sheet 15
SDMMC0_D1: J30.172(P172) ; also on sheet 15
SDMMC0_D2: J30.170(P170) ; also on sheet 15
SDMMC0_D3: J30.168(P168) ; also on sheet 15
SDMMC0_DET_L: J30.166(P166) ; also on sheet 15
SPKN_OUT: J30.236(P236) ; also on sheet 14
SPKP_OUT: J30.238(P238) ; also on sheet 14
SS_TXN: C114.1 J15.8(TX-) U19.2(D1-) U19.9(NC2)
SS_TXP: C115.1 J15.9(TX+) U19.1(D1+) U19.10(NC1)
UART1_DIR: J30.184(P184) R75.1 U14.2(~{RE}) U14.3(DE)
UART1_RX_M0: J30.194(P194) R69.2 U14.1(RXD)
UART1_TX_M0: J30.196(P196) R67.2 U14.4(TXD)
UART2_RX_M0_DEBUG: J30.156(P156) ; also on sheet 19
UART2_TX_M0_DEBUG: J30.158(P158) ; also on sheet 19
UART3_RX_M1: J30.52(P52) ; also on sheet 15
UART3_TX_M1: J30.54(P54) ; also on sheet 15
UART4_RX_M1: J30.48(P48) ; also on sheet 15
UART4_TX_M1: J30.50(P50) ; also on sheet 15
UART6_DIR: J30.182(P182) R77.1 U15.2(~{RE}) U15.3(DE)
UART6_RX_M0: J30.190(P190) R70.2 U15.1(RXD)
UART6_TX_M0: J30.192(P192) R68.2 U15.4(TXD)
UART7_RX_M0: J30.186(P186) ; also on sheet 16
UART7_TX_M0: J30.188(P188) ; also on sheet 16
UART9_RX_M1: J30.98(P98) ; also on sheet 16
UART9_TX_M1: J30.100(P100) ; also on sheet 16
USB2_HOST2_DM: J30.7(P7) R126.1
USB2_HOST2_DP: J30.9(P9) R125.1
USB2_HOST3_DM: J30.11(P11) R143.2
USB2_HOST3_DP: J30.13(P13) R142.2
USB3_HOST1_DM: J30.3(P3) R136.2
USB3_HOST1_DP: J30.5(P5) R137.2
USB3_HOST1_SSRXN: J15.5(RX-) J30.201(P201) U18.2(D1-) U18.9(NC2)
USB3_HOST1_SSRXP: J15.6(RX+) J30.199(P199) U18.1(D1+) U18.10(NC1)
USB3_HOST1_SSTXN: C114.2 J30.197(P197)
USB3_HOST1_SSTXP: C115.2 J30.195(P195)
USB20_HOST_PWR_EN: J30.28(P28) R141.1
USB20_OTG_PWR_EN: J30.138(P138) R150.1
USB30_HOST_PWR_EN: J30.41(P41) R147.1
USB OTG: C125.1 C126.1 J16.A4(VBUS1) J16.A9(VBUS2) J16.B4(VBUS4) J16.B9(VBUS3) R149.1 U25.1(OUT)
USB_OTG0_DM: J30.203(P203) R134.2
USB_OTG0_DP: J30.205(P205) R135.2
USB_OTG0_ID: J30.160(P160) R138.2
USB_OTG0_VBUSDET: J30.162(P162) R149.2 R151.1
USER_LED: J30.142(P142) ; also on sheet 19
WLAN_PWR_EN: J30.151(P151) R128.1
N15599533: R96.2 U16.25(RXD0)
N15599537: R97.2 U16.24(RXD1)
N15599541: R99.2 U16.23(RXD2)
N15599545: R100.2 U16.22(RXD3)
N15599549: R101.2 U16.27(RXC)
N15599553: R102.2 U16.26(RXCTL)
N15599792: R90.2 R91.1 R93.1 R94.1 R95.1
N15600759: R106.2 R107.1 R108.1 R109.1
N15600826: R110.2 R112.2 U16.31(INTB)
N15601838: C83.1 U16.37(XTAL_OUT) Y1.1
N15601846: C84.1 U16.36(XTAL_IN) Y1.3
N15602572: R118.1 U16.32(LED0)
N15602600: R117.2 R121.2 R122.1
N15603170: C85.1 J14.1(CT)
N15605512: R98.1 U16.39(RSET)
N15605755: C79.1 C80.1 R89.1 R92.1 U16.28(DVDD_RG)
N15611443: C118.1 R141.2 U21.4(EN)
N15611553: R144.1 U21.3(ISET)
N15653247: C124.1 R150.2 U25.4(EN)
N15653357: R153.1 U25.3(ISET)
N15653957: C121.1 R147.2 U24.4(EN)
N15654067: R148.1 U24.3(ISET)
N15752445: L9.1 U26.G1(20) U26.G2(21) U26.G3(22) U26.G4(23)
N15772454: J19.14 R162.2
N15774097: J18.14 R161.2
N15980269: J10.2 R73.2
N17430242: R34.1 U7.3(ISET)
N17430314: C47.1 R33.2 U7.4(EN)
N17443353: R32.1 U6.3(ISET)
N17443371: C41.1 R31.2 U6.4(EN)
N17444423: C38.2 Q4.1(GATE) Q5.1(GATE) Q6.3(COLLECTOR) R27.2
N17444523: Q6.1(BASE) R29.2 R30.1
N17466585: L4.1 U16.30(REG_OUT)
N17633217: C119.1 U22.3(XOUT) Y2.1
N17633237: C120.2 U22.4(XIN) Y2.3
N17633305: R145.2 U22.16(RESET#/CDP)
N17633317: R146.2 U22.18(PSELF)
N17695706: C139.1 R172.2 U29.4(EN) U31.4(EN)
N17695791: R175.1 U31.3(ISET)
N17695827: R174.1 U29.3(ISET)
N17697466: J14.13(YELC) R114.1
N17701231: J11.2 R74.2
N17702194: J12.3 R81.2
N17702199: J12.4 R82.2
N17702222: J12.2 R80.2
N17702231: J12.1 R79.2
N17728858: D19.1 R71.1
N17729021: D20.1 R72.1
N17748815: Q5.2(SOURCE) R26.2
N17770939: R142.1 U22.15(DPU)
N17770942: R143.1 U22.14(DMU)
N18056005: C109.2 Q7.1(GATE) R127.2 R128.2
N18056634: C106.1 C107.1 U17.2(RF0)
N18056637: C106.2 C108.1 CN1.1
N18057325: R126.2 U17.7(D-)
N18057335: R125.2 U17.6(D+)
N18111918: C136.1 R171.2 U30.4(EN) U32.4(EN)
N18111989: R176.1 U32.3(ISET)
N18112037: R173.1 U30.3(ISET)
N18173560: J16.C1(SH1) J16.C2(SH2) J16.C3(SH3) J16.C4(SH4) L8.1
N18175084: D26.3 R138.1
N18341998: J14.12(GRLC) R111.1
N18461230: Q4.2(SOURCE) R26.1

Not connected (* = marked no-connect by the designer): J15 14(NC1)* 15(NC2)* 17(NC4)* 18(NC5)*; J16 A8(SBU1)* B8(SBU2)*; J30 19(P19)* 21(P21)* 27(P27)* 29(P29)* 32(P32)* 51(P51)* 65(P65)* 67(P67)* 69(P69)* 71(P71)* 73(P73)* 75(P75)* 96(P96)* 153(P153)* 213(P213)* 215(P215)* 217(P217)* 219(P219)*; U17 3(RF1)* 4(XIN)* 9(SUSPEND)* 10(WO_WLAN)* 11(BT_PCM_CLK)* 12(BT_PCM_SYNC)* 13(BT_PCM_OUT)* 14(BT_PCM_IN)*; U22 2(NC1)* 13(LED3/SCL)* 17(NC2)* 19(VDD5)* 21(LED4/SDA)* 22(LED1)* 23(LED2)* 24(PWREN#)*; U26 14*

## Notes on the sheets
sheet 1
- WLAN & BT
- Z0=50Ω
- WLAN Power
- GPIO0_D5
sheet 2
- 野火_EBF RK3566 底板_原理图
- 目录
- Page 1
- Content
- Page 2
- Historic Version
- Page 3
- POWER DIAGRAM
- Page 4
- DC IN/POWER/FAN
- Page 5
- POWER OUT PORT
- Page 6
- DDR4 Connector
- Page 7
- Button/FLASH/IR/DEBUG/LED
- Page 8
- SD/RTC/RS232
- Page 9
- WIFI&Bluetooth
- Page 10
- ETH
- Page 11
- USB PORT
- Page 12
- HDMI PORT
- Page 13
- MIPI DSI/eDP1.3/TP_PORT
- Page 14
- MIPI CSI PORT
- Page 15
- eDP_1.3/TP_PORT
- Page 16
- MINI PCIE_PORT
- Page 17
- AUDIO PORT
- Page 18
- RS485 PORT
sheet 3
- 历史版本
- 版本号
- 日期
- 设计
- 描述
- V1.0
- 2022-07-07
- ghs
- 初始版本
sheet 4
- VCC12V_EDP
- PMOS
- EDP Power
- VCC12V_OUT
- PMOS
- Power OUT
- Switch
- OCP：1A
- EDP_PORT
- Switch
- DC-DC
- OCP：1A
- MIPI_PORT
- VCC3V3_SYS
- 3.3V 3A
- Switch
- Power OUT
- OCP：1A
- ETH
- UART7
- RS232
- SYS_Switch
- VDD_3V3
- WIFI&BT
- UART9
- RS485_1
- OCP：2A
- LED
- RTC
- RS485_2
- IR PORT
- HDMI_PORT
- USB2.0 HUB PHY
- Switch
- MIPI_CSI
- OCP：1A
- Switch
- MIPI_DSI_1
- DC IN
- DC-DC
- OCP：2A
- MIPI_DSI_2
- VCC5V0_SYS
- 12V 3A
- 5V 3A
- Core Top Plate
- SYS_Switch
- VDD_5V
- HDMI_PORT
- OCP：1A
- Switch
- USB2.0_PORT
- OCP：2A
- Switch
- USB3.0_OTG
- OCP：2A
- DC-DC
- VCC5V0_SYS_2
- 5V 3A
- Switch
- USB2.0_HOST
- OCP：2A
- Switch
- Power OUT
- OCP：1A
- FAN
- NC
- DC-DC
- MINIPCIE_3V3
- MINI_PCIE
- 3.3V 3A
sheet 5
- Power OutPut SW
- Power Output
- OCP：3.3V 1A
- OCP：5V 1A
- 1.5A熔断
- GPIO0_D3
- 1.8V IO
- GPIO3_C1
- 1A限流
- GPIO0_C5
- 1A限流
sheet 6
- BD ID
- Board ID:09
- BD_CH3:0.507V
- ADC值:288
- GPIO0_C0
- GPIO0_C5
- GPIO0_C6
- GPIO0_C7
- GPIO4_C5
- PWM12_M1
- GPIO4_C6
- PWM13_M1
- GPIO3_C5
- PWM15_IR_M0
- EDP_TX_D2N
- EDP_TX_D2P
- IO:1V8
- IO:1V8
- EDP_TX_D3P
- IO:1V8
- EDP_TX_D3N
- IO:1V8
- IO:1V8
- GPIO3_C6
- SDMMC2_D0_M0
- IO:1V8
- GPIO3_C7
- SDMMC2_D1_M0
- GPIO3_D0
- SDMMC2_D2_M0
- IO:1V8
- IO:1V8
- GPIO3_D1
- GPIO3_D2
- SDMMC2_CMD_M0
- SDMMC2_D3_M0
- IO:1V8
- GPIO3_D3
- SDMMC2_CLK_M0
- GPIO4_C0
- GPIO2_B5
- GPIO3_D4
- GPIO2_B6
- GPIO3_D5
- GPIO4_C2
- GPIO4_C3
- LED3
- GPIO2_C1
- GPIO2_C2
- GPIO3_C1
- PWM_M0
- GPIO2_C3
- GPIO3_C2
- PWM4
- GPIO2_C4
- GPIO2_C5
- GPIO3_C3
- GPIO3_C4
- PWM5
- GPIO2_C6
- GPIO3_A1
- GPIO2_A7
- GPIO3_A2
- GPIO2_B0
- GPIO3_A3
- GPIO0_A6
- GPIO2_B1
- GPIO3_A4
- IO:1V8
- GPIO0_D6
- GPIO2_B2
- GPIO3_A5
- IO:1V8
- IO:1V8
- GPIO0_D4
- GPIO0_D5
- LED2
- GPIO3_A6
- GPIO3_A7
- IO:1V8
- GPIO0_D3
- GPIO3_B6
- GPIO3_B0
- GPIO1_A4
- GPIO1_B0
- GPIO1_B1
- GPIO1_B2
sheet 7
- RS485-1
- RS485-2
- GPIO2_B5
- GPIO2_B6
- RS485 PORT
sheet 8
- ETH
- TXC / RXC : delays 2ns
- PHY Address : 010
- IO use an external
  power supply：3.3V
- L:<200mils
  W:>60mils
- L:<200mils
  W:>60mils
- L:<200mils
- W:>60mils
- GPIO4_C2
- GPIO0_A6
sheet 9
- USB3.0 HOST & OTG
- USB2.0 HOST
- TYPE-C OTG
- HOST Power
- USB 2.0 HUB PHY
- GPIO3_A1
- 2A限流
- GPIO4_C3
- 2A限流
- GPIO0_C6
- 1A限流
sheet 10
- HDMI2.0 PORT
- KLXES15AAA1*4
sheet 11
- MIPI_DSI_TX0 PORT
- MIPI_DSI_TX1 PORT
- Default:LVDS
- Default:MIPI DSI
- GPIO3_C4
- GPIO3_C2
- PWM4
- GPIO2_C3
- GPIO3_A4
- GPIO2_C4
- PWM5
- GPIO3_A3
- GPIO2_C1
- GPIO2_C2
- MIPI DSI Power
- GPIO3_D5
- GPIO1_A4
- 1A限流
- 1A限流
- 1A限流
- 1A限流
